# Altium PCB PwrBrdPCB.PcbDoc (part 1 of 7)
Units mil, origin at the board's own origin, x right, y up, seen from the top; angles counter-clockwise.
Board outline 8000 x 5500 mil, 4 copper layers (Top Layer, Internal 1, Internal 2, Bottom Layer), stack 61.834 mil thick; 682 components, 380 nets, 1899 pads, 766 vias.
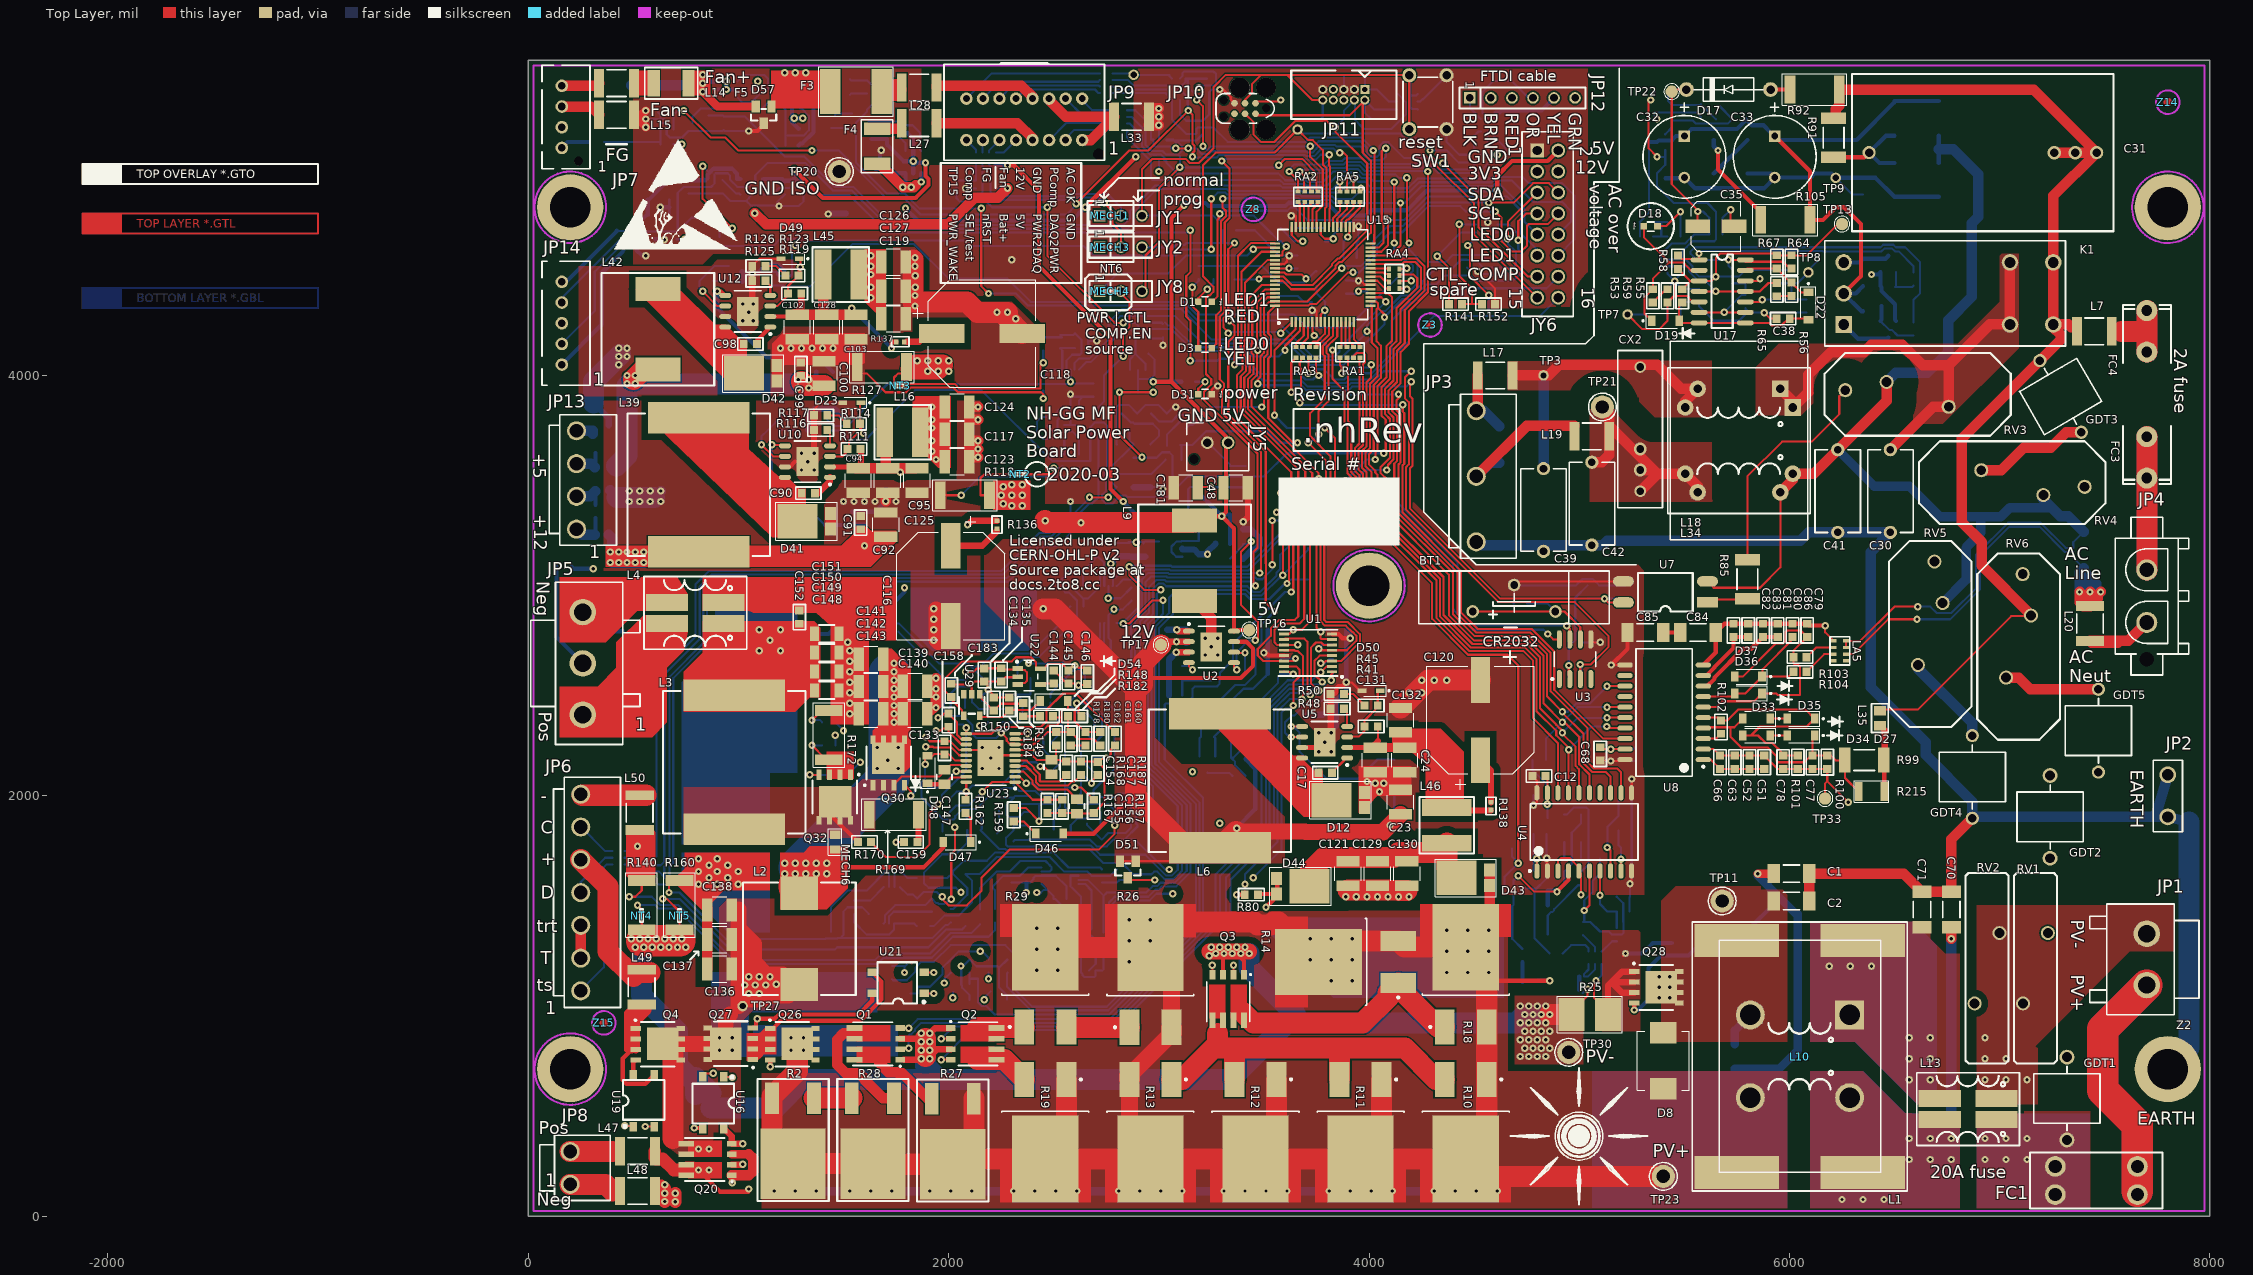
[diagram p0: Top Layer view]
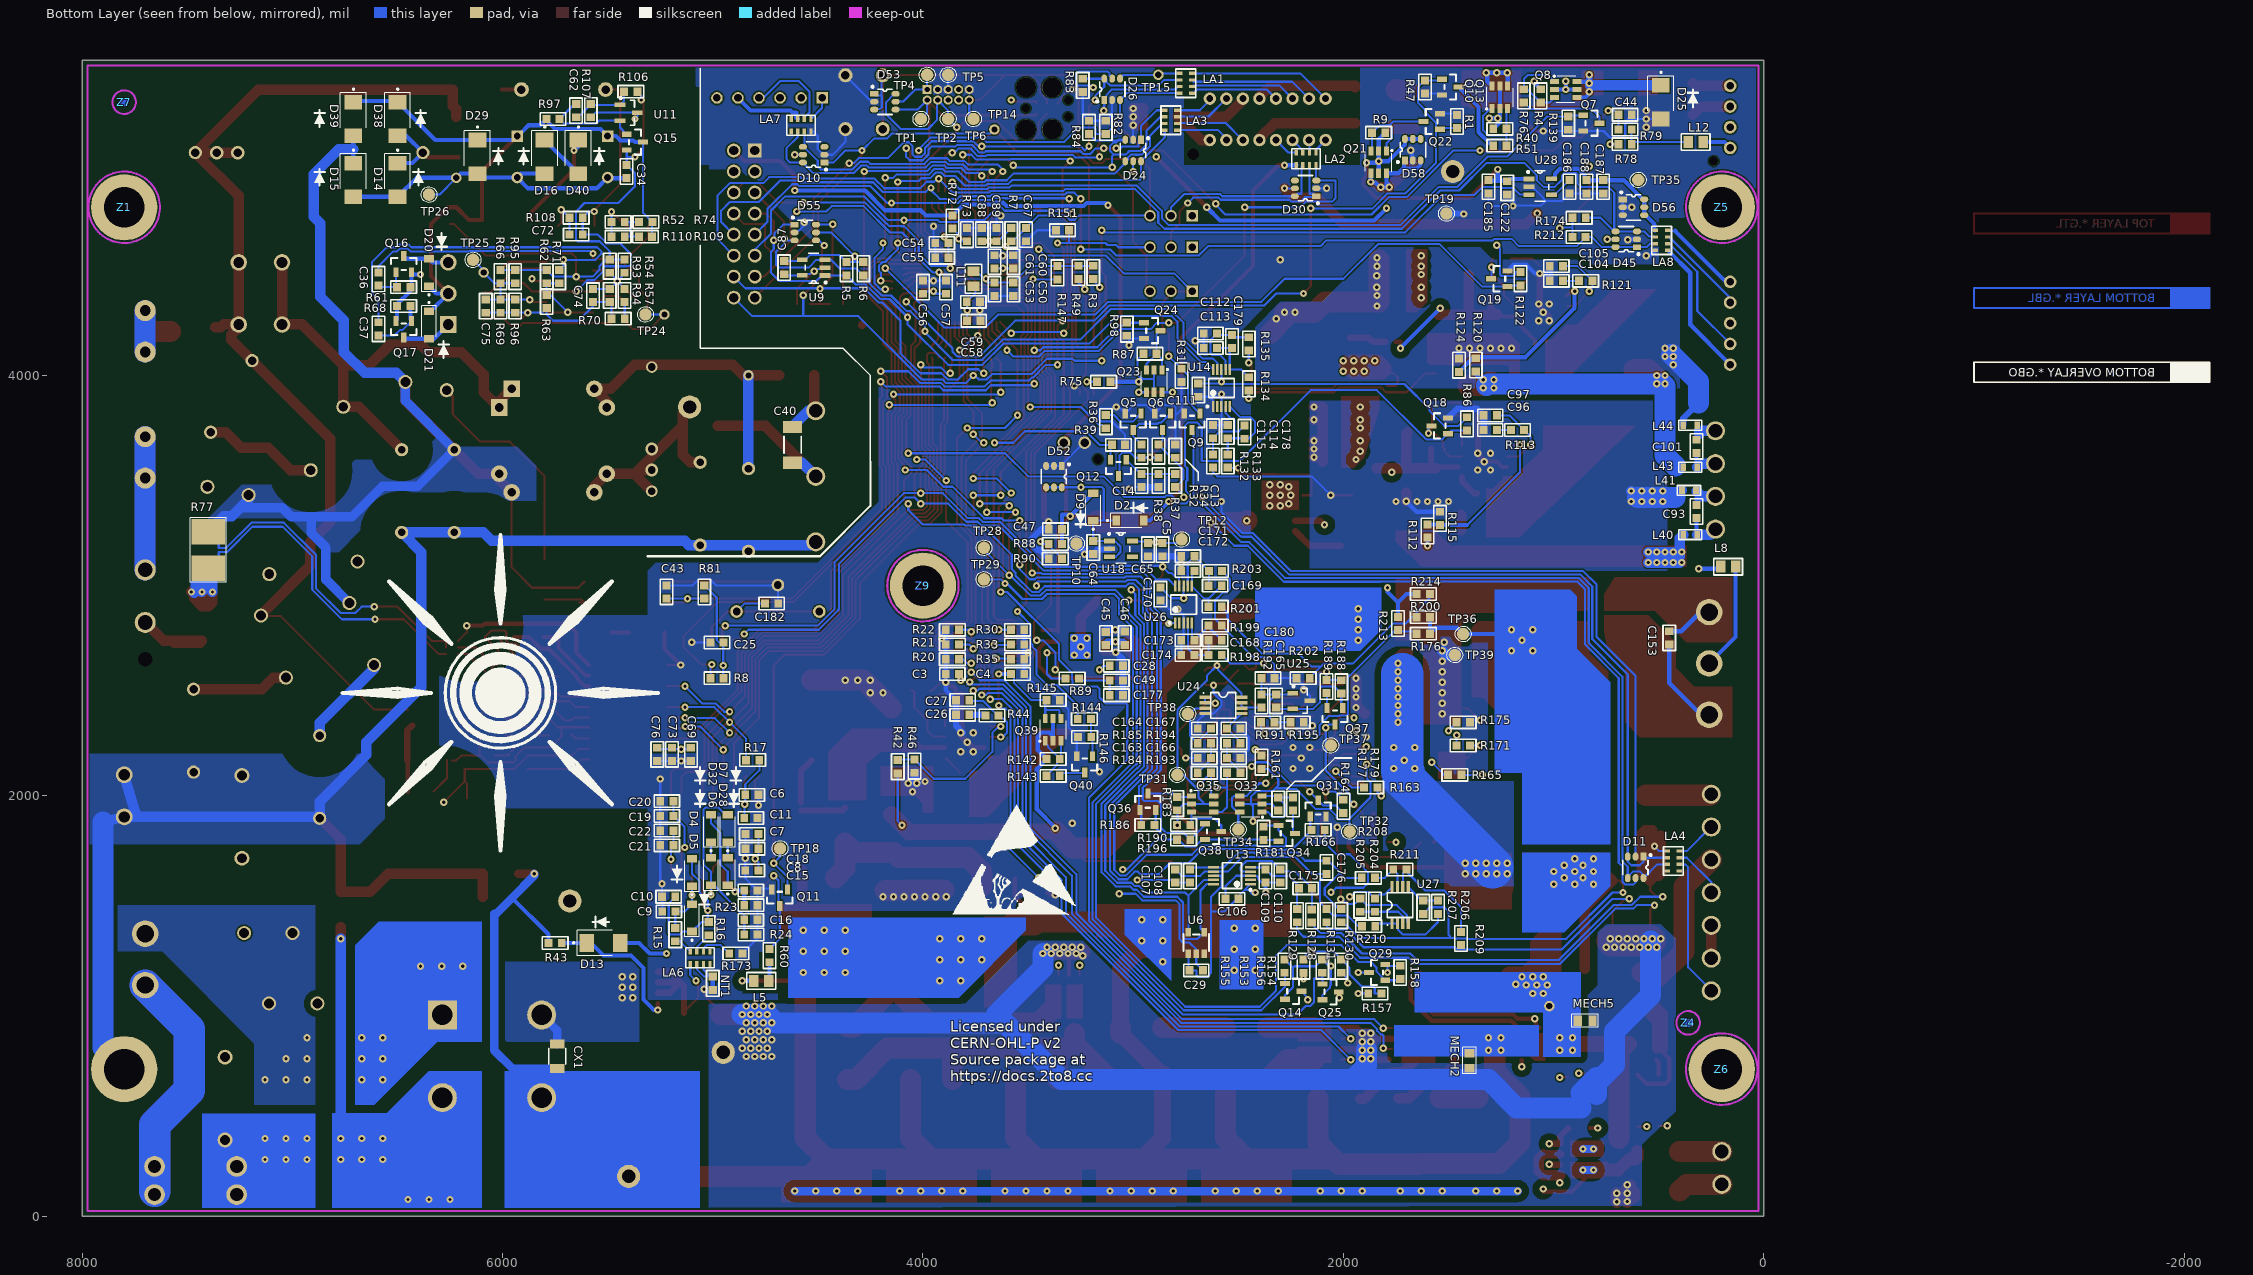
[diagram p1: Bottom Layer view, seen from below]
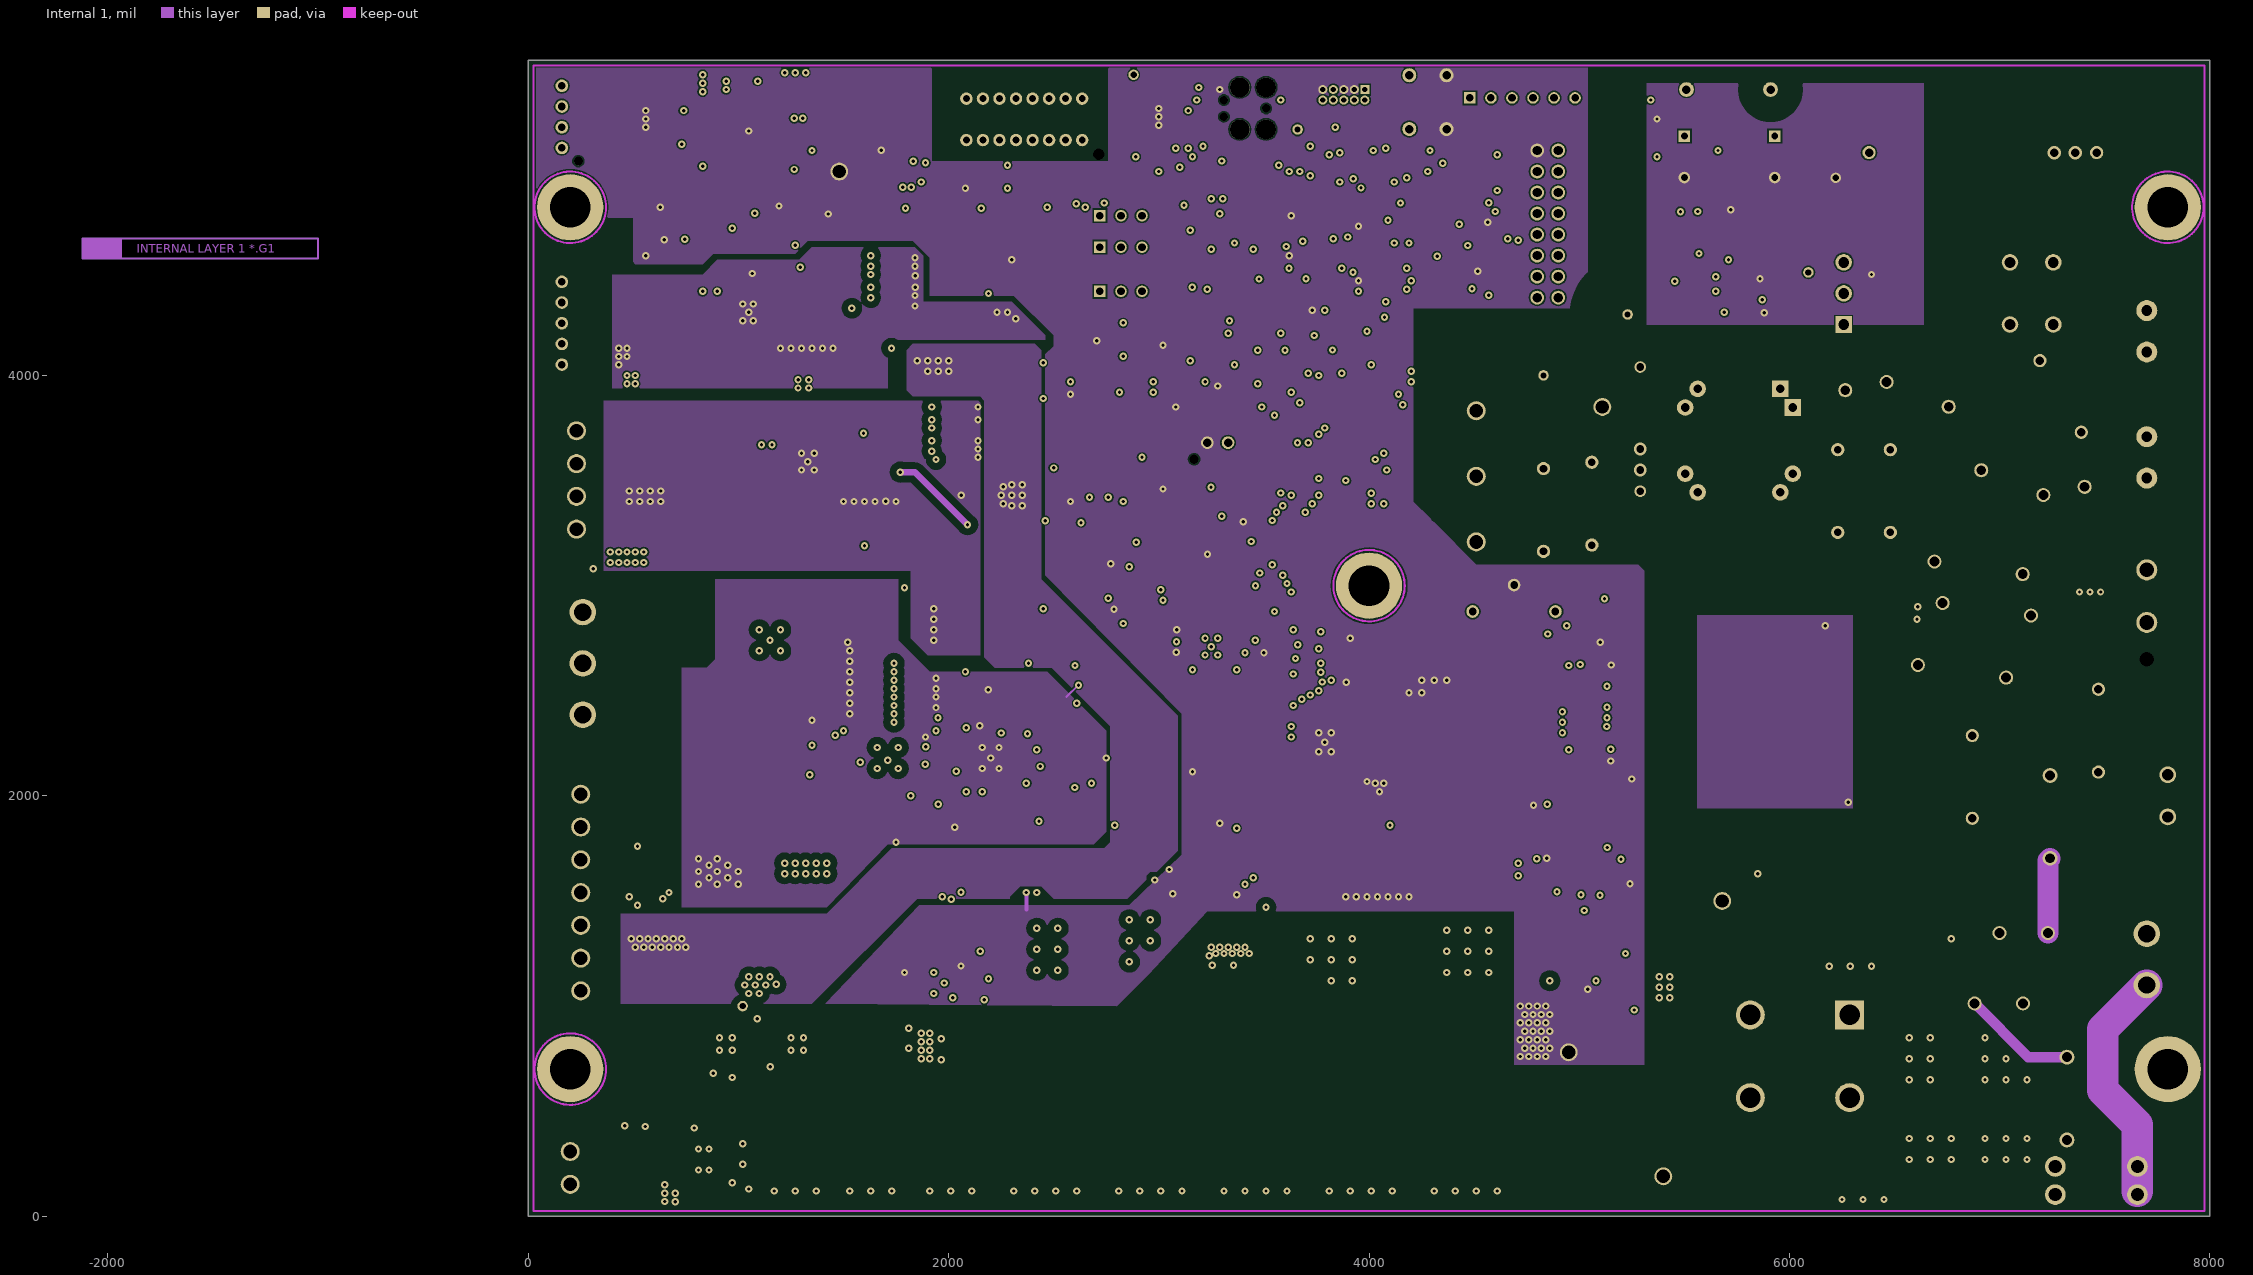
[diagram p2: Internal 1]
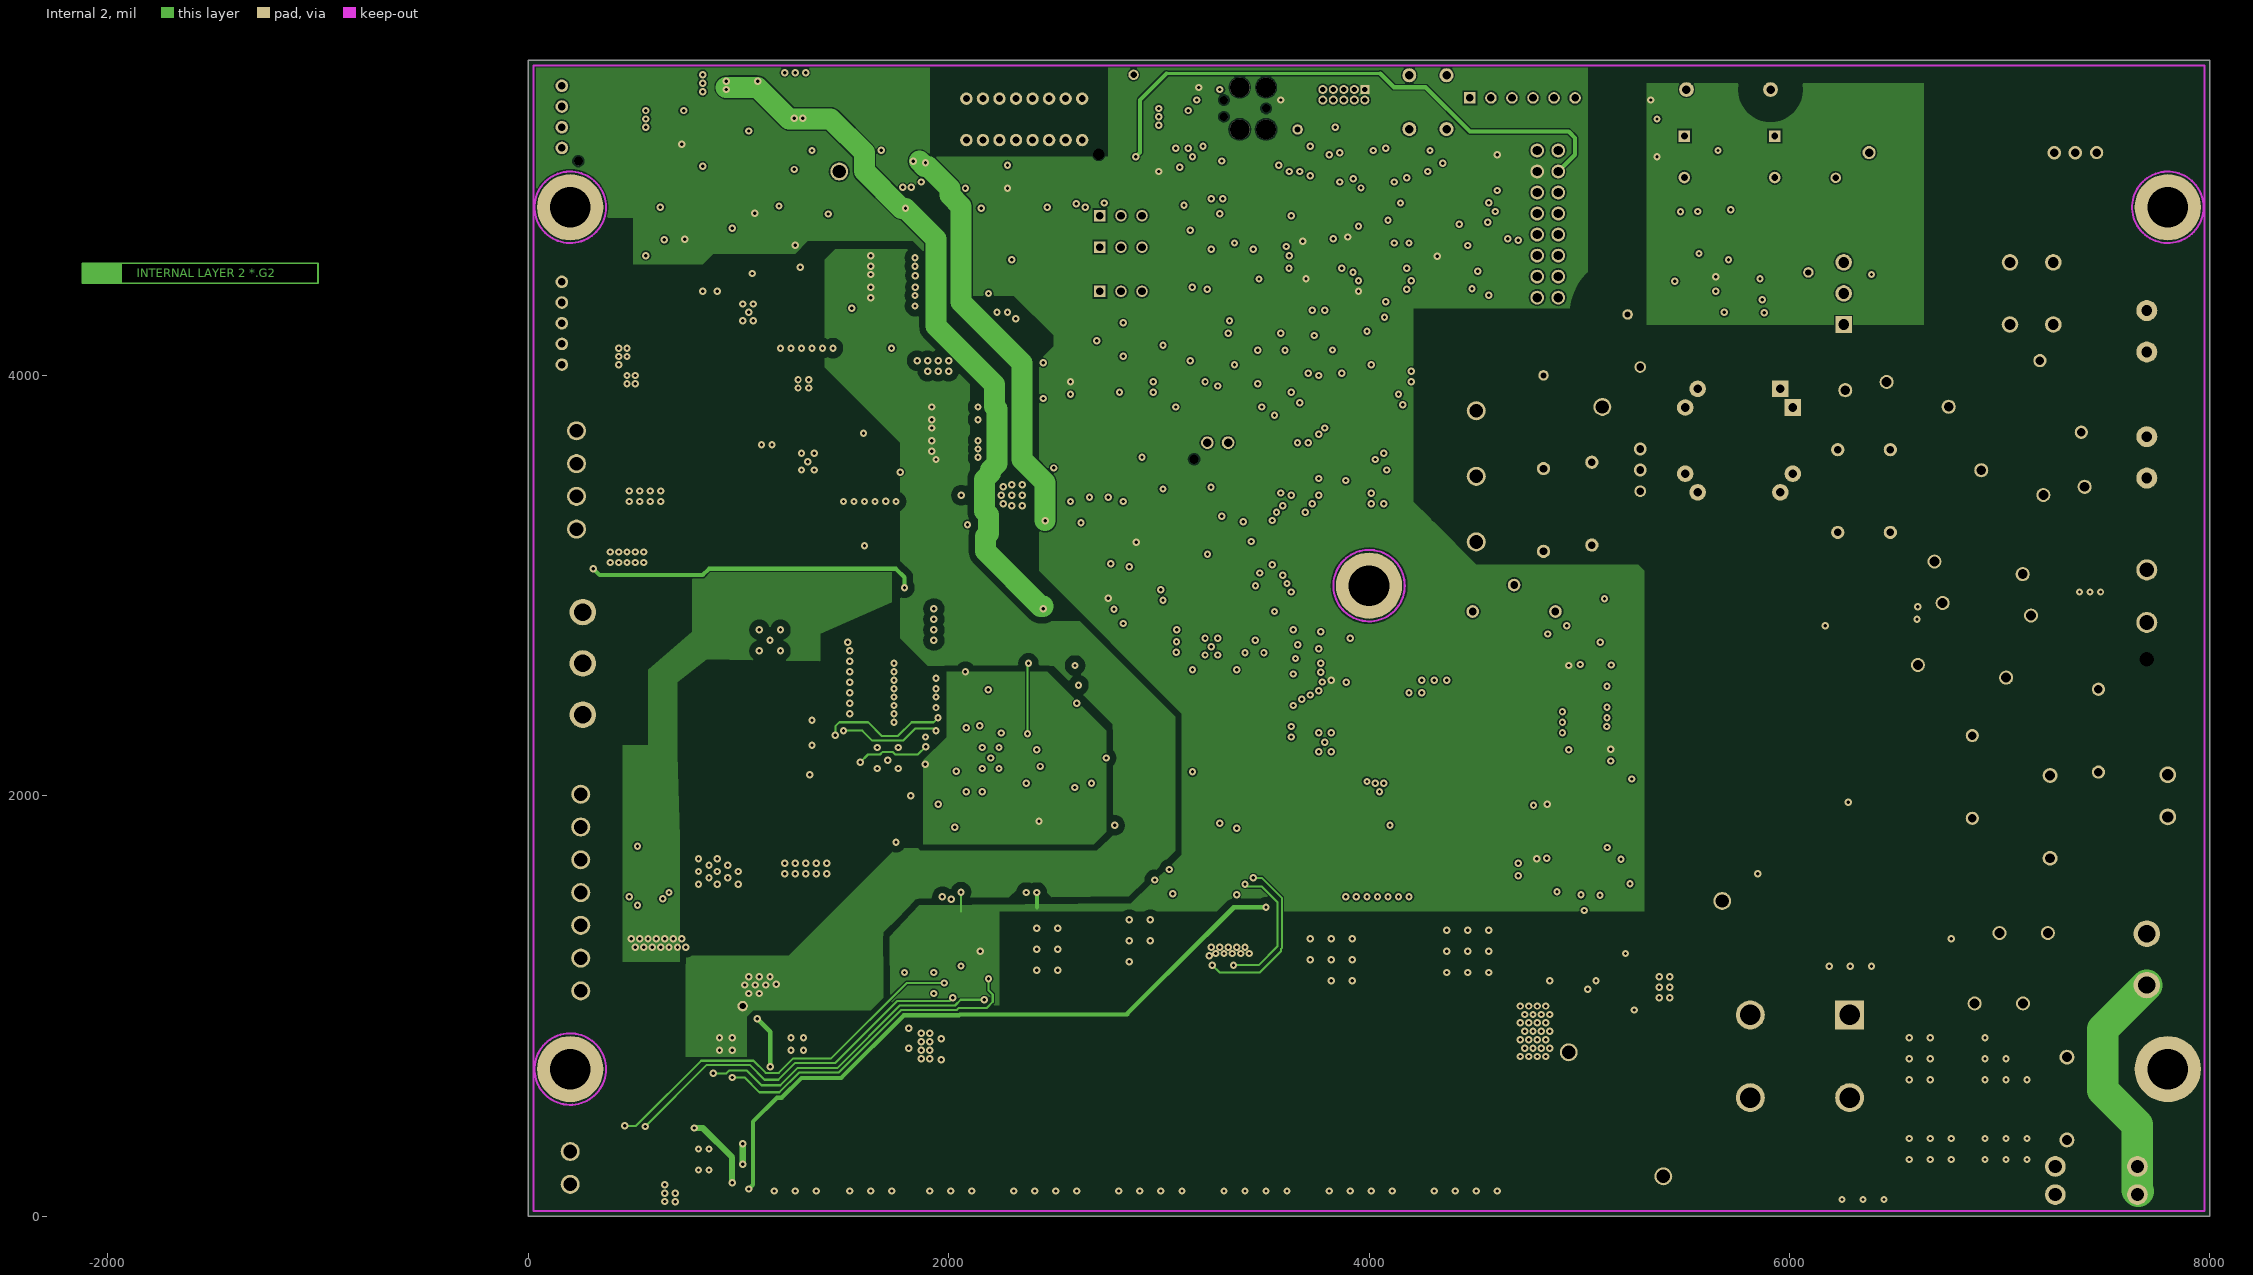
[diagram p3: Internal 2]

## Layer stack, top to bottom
Top Solder: solder mask 0.4, Solder Resist, Dk 3.5
Top Layer: signal copper 1.4
Dielectric 1: core 14.1, FR-4, Dk 4.2
Internal 1: signal copper 1.417
Dielectric 3: prepreg 28, FR-4, Dk 4.2
Internal 2: signal copper 1.417
Dielectric 2: core 14.1, FR-4, Dk 4.2
Bottom Layer: signal copper 1.4
Bottom Solder: solder mask 0.4, Solder Resist, Dk 3.5

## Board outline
0,0 0,5500 8000,5500 8000,0 3900,0 3500,0

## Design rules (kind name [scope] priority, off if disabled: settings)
AssemblyTestPointUsage [All] p1 off:
AssemblyTestpoint [All] p1 off: testpointundercomponent=TRUE minsize=40 maxsize=100 preferedsize=60 minholesize=0 maxholesize=40 preferedholesize=32 testpointgrid=1 usegrid=TRUE gridtolerance=0.01 allowsidetop=TRUE allowsidebottom=TRUE
Clearance Clearance_PVSELV [InNetClass('PVPOS') vs InNetClass('SELV')] p1: gap=32 ignorepadtopadclearanceinfootprint=TRUE // Super reinforced for separated extremely low voltage
Clearance Clearance_ProtCtl [InNetClass('LineUnprot') OR InNetClass('Neut') vs InNetClass('ProtCtrl')] p2: gap=120 ignorepadtopadclearanceinfootprint=TRUE // "functional" insulation for protection control traces
Clearance Clearance_LineSELV [InNetClass('LineProt') OR InNetClass('Neut') OR InNetClass('LineUnprot') OR InNetClass('ProtCtrl') vs InNetClass('SELV')] p3: gap=252 ignorepadtopadclearanceinfootprint=FALSE // Super reinforced for separated extremely low voltage
Clearance Clearance_PVtoEarth [InNetClass('PVPOS') vs InNetClass('Earth')] p4: gap=52 ignorepadtopadclearanceinfootprint=FALSE except(0: Arc-Hole Track-Hole SMDPad-Hole THPad-Hole Via-Hole Fill-Hole Poly-Hole Region-Hole Text-Hole) // "basic" insulation for PV to earth
Clearance Clearance_LProtToEarth [InNetClass('LineProt') vs InNetClass('Earth')] p5: gap=126 ignorepadtopadclearanceinfootprint=TRUE // "basic" insulation for protected side to earth
Clearance Clearance_LNUnprotEarth [InNetClass('LineUnprot') OR InNetClass('Neut') vs InNetClass('Earth')] p6: gap=166 ignorepadtopadclearanceinfootprint=TRUE // "basic" insulation for unprotected parts to Earth
Clearance Clearance_LNProt [InNetClass('LineProt') vs InNetClass('Neut')] p7: gap=118 ignorepadtopadclearanceinfootprint=TRUE // "functional" insulation for partsProtected by relay
Clearance Clearance_LUnProtN [InNetClass('LineUnprot') vs InNetClass('Neut')] p8: gap=166 ignorepadtopadclearanceinfootprint=TRUE // "basic" insulation for LN before relay
Clearance Clearance_innerPlanes [(OnLayer('Grounds') OR OnLayer('Powers'))] p9: gap=11 ignorepadtopadclearanceinfootprint=FALSE
Clearance [All] p10: gap=7 ignorepadtopadclearanceinfootprint=FALSE except(0: Arc-Hole Track-Hole SMDPad-Hole THPad-Hole Via-Hole Fill-Hole Poly-Hole Region-Hole Text-Hole)
FabricationTestPointUsage [All] p1 off: valid=0 allowmultiple=FALSE
FabricationTestpoint [All] p1 off: side=3 testpointundercomponent=TRUE minsize=40 maxsize=100 preferedsize=60 minholesize=0 maxholesize=40 preferedholesize=32 testpointgrid=1 allowsidetop=TRUE allowsidebottom=TRUE usegrid=TRUE gridtolerance=0.01
Height [All] p1 off: minheight=0 maxheight=1000 prefheight=500
HoleSize [All] p1: absolutevalues=TRUE maxlimit=200 minlimit=1 maxpercent=80.000 minpercent=20.000
PolygonConnect [All] p1: connectstyle=Direct reliefconductorwidth=10 reliefentries=4 polygonreliefangle="90 Angle" airgapwidth=10
RoomDefinition 12Vmain [InComponentClass('12Vmain')] p1: confinementstyle=ConfineIn formatcopy=TRUE lockcomponents=FALSE outline 2936.97,1664.23 2936.97,2479.63 3737.52,2479.63 3737.52,2498.94 3773.82,2498.94 3773.82,2528.46 4243.43,2528.46 4243.43,2690.28 4816.57,2690.28 4816.57,2017.5 4618.56,2017.5 4618.56,1507.58 3835.12,1507.58 3835.12,1468.22 3518.13,1468.22 3518.13,1486.53 3375.04,1486.53 3375.04,1664.23
RoomDefinition 5Vmain [InComponentClass('5Vmain')] p2: confinementstyle=ConfineIn formatcopy=TRUE lockcomponents=FALSE outline 2886.61,2835.47 2886.61,3401.54 3453.63,3401.54 3453.63,2838.86 3480.36,2838.86 3480.36,2738.15 3406.66,2738.15 3406.66,2589.25 3364.96,2589.25 3364.96,2515.04 3153.98,2515.04 3153.98,2505.04 3153.98,2435.04 3006.02,2435.04 3006.02,2668.15 2959.65,2668.15 2959.65,2835.47
RoomDefinition 3V3sup [InComponentClass('3V3sup')] p3: confinementstyle=ConfineIn formatcopy=TRUE lockcomponents=FALSE outline 2939.64,3361.85 3040.35,3361.85 3040.35,3266.16 3419.22,3266.16 3419.22,3043.23 3231.66,3043.23 3231.66,3094.08 2960.05,3094.08 2960.05,3097.52 2816.53,3097.52 2816.53,3245.47 2939.64,3245.47
RoomDefinition DCInput [InComponentClass('DCInput')] p4: confinementstyle=ConfineIn formatcopy=TRUE lockcomponents=FALSE outline 5261.21,537.94 5261.21,942.4 5415.04,942.4 5415.04,1513.47 5597.17,1513.47 5597.17,1582.83 5875,1582.83 5875,1696.1 7068.58,1696.1 7068.58,2149.17 7715.2,2149.17 7715.2,2183.94 7884.8,2183.94 7884.8,1499.76 7961.97,1499.76 7961.97,944.33 7789.96,944.33 7789.96,21.14 7130.04,21.14 7130.04,105.24 5522.4,105.24 5522.4,107.17 5317.17,107.17 5317.17,537.94
RoomDefinition PVMon [InComponentClass('PVMon')] p5: confinementstyle=ConfineIn formatcopy=TRUE lockcomponents=FALSE outline 4622.93,1371.01 4622.93,1528.6 4734.53,1528.6 4734.53,2138.11 4882.48,2138.11 4882.48,2070.91 5302.2,2070.91 5302.2,1445 5308.86,1445 5308.86,1344.29 5221.97,1344.29 5221.97,1265.04 5141.42,1265.04 5141.42,1152.99 4981.97,1152.99 4981.97,1066.53 4841.34,1066.53 4841.34,1046.69 4675.67,1046.69 4675.67,1371.01
RoomDefinition ACMon [InComponentClass('ACMon')] p6: confinementstyle=ConfineIn formatcopy=TRUE lockcomponents=FALSE outline 5060.63,2123.27 5060.63,2271.22 5161.81,2271.22 5161.81,2721.22 5179.09,2721.22 5179.09,2843.35 5690.63,2843.35 5690.63,2861.22 6127.56,2861.22 6127.56,2738.9 6160.71,2738.9 6160.71,2416.47 6178.76,2416.47 6178.76,2400.55 6466.93,2400.55 6466.93,2293.94 6461.26,2293.94 6461.26,2100.16 6219.88,2100.16 6219.88,1936.89 6117.56,1936.89 6117.56,1932.28 5890.63,1932.28 5890.63,1933.27 5820.63,1933.27 5610.63,1933.27 5610.63,1934.76 5540.63,1934.76 5540.63,2073.27 5161.81,2073.27 5161.81,2123.27
RoomDefinition ACInput [InComponentClass('ACInput')] p7: confinementstyle=ConfineIn formatcopy=TRUE lockcomponents=FALSE outline 4354.32,3116.06 4354.32,3923.94 4472.87,3923.94 4472.87,4089.72 5169.76,4089.72 5169.76,4132.68 5418.23,4132.68 5418.23,4177.44 6153.22,4177.44 6153.22,4653.94 7326.77,4653.94 7326.77,4373.94 7829.17,4373.94 7829.17,4028.27 7838.94,4028.27 7838.94,3338.94 7913.94,3338.94 7913.94,2561.06 7641.42,2561.06 7641.42,2064.76 7041.42,2064.76 7041.42,1844.76 6698.58,1844.76 6698.58,2301.34 6458.15,2301.34 6458.15,3109.84 4705.83,3109.84 4705.83,3116.06
RoomDefinition Aux12V [InComponentClass('Aux12V')] p8: confinementstyle=ConfineIn formatcopy=TRUE lockcomponents=FALSE outline 457.91,3072.3 457.91,3887.7 1940.02,3887.7 1940.02,3924.96 2139.7,3924.96 2139.7,3517.76 2243.62,3517.76 2243.62,3345.28 2267.56,3345.28 2267.56,3341.56 2296.57,3341.56 2296.57,2668.78 1723.43,2668.78 1723.43,3072.3
RoomDefinition U_HVAUX [InComponentClass('U_HVAUX')] p9: confinementstyle=ConfineIn formatcopy=TRUE lockcomponents=FALSE outline -1.97,2230.24 -1.97,3029.76 87.17,3029.76 87.17,3143.31 252.83,3143.31 252.83,3058.23 1054.06,3058.23 1054.06,2923.98 1333.46,2923.98 1333.46,2894.96 1783.47,2894.96 1783.47,2658.12 2480.6,2658.12 2480.6,2641.39 2713.46,2641.39 2713.46,2440.35 2790.35,2440.35 2790.35,2345.48 2834.96,2345.48 2834.96,2150.35 2840.35,2150.35 2840.35,2050.1 3006.44,2050.1 3006.44,1892.51 3004.96,1892.51 3004.96,1818.03 2834.96,1818.03 2834.96,1748.03 2423.46,1748.03 2423.46,1746.54 2348.99,1746.54 2348.99,1745.92 2164.67,1745.92 2164.67,1731.66 1573.63,1731.66 1573.63,1003.9 1006.61,1003.9 1006.61,1101.57 810.3,1101.57 810.3,1313.5 632.24,1313.5 632.24,1752.3 626.42,1752.3 626.42,2230.24
RoomDefinition Aux5V [InComponentClass('Aux5V')] p10: confinementstyle=ConfineIn formatcopy=TRUE lockcomponents=FALSE outline 333.49,3936.97 333.49,4503.03 913.15,4503.03 913.15,4563.47 1022.16,4563.47 1338.27,4563.47 1338.27,4624.92 1635.98,4624.92 1635.98,4614.96 1836.82,4614.96 1836.82,4486.57 2489.33,4486.57 2489.33,2421.97 2540.76,2421.97 2540.76,2335.04 2390.84,2335.04 2390.84,3910.02 1332.17,3910.02 1332.17,3936.97
RoomDefinition U_ACProtection [InComponentClass('U_ACProtection')] p11: confinementstyle=ConfineIn formatcopy=TRUE lockcomponents=FALSE outline 5195,4255 5195,4325 5243.54,4325 5243.54,4773.47 5282.31,4773.47 5282.31,5309.84 5312.24,5309.84 5312.24,5339.72 5315.04,5339.72 5315.04,5393.47 5389.65,5393.47 5389.65,5400.35 5459.84,5400.35 5459.84,5429.06 5953.5,5429.06 5953.5,5447.76 6282.95,5447.76 6282.95,5449.02 7557.05,5449.02 7557.05,4670.98 6633.47,4670.98 6633.47,4147.52 6545.58,4147.52 6545.58,4141.4 6393.56,4141.4 6393.56,4141.73 6301.66,4141.73 6301.66,4199.58 5508.69,4199.58 5508.69,4210.77 5285.33,4210.77 5285.33,4239.65 5269.65,4239.65 5269.65,4255
RoutingVias [All] p1: holewidth=16 width=35 viastyle="Through Hole" minholewidth=16 minwidth=35 maxholewidth=50 maxwidth=70
SMDNeckDown [All] p1: percent=90.000
SilkToSilkClearance [All] p1 off: silktosilkclearance=10
SilkToSolderMaskClearance [IsPad] p1: minsilkscreentomaskgap=5 clearancetoexposedcopper=TRUE
SolderMaskExpansion [All] p1: expansion=4 istentingtop=FALSE
Width WidthPVPos [InNetClass('PVPOS')] p1: maxlimit=200 minlimit=20 preferedwidth=20
Width [All] p2: maxlimit=300 minlimit=7 preferedwidth=10
22 further rules are at their usual default settings.

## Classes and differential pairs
component class U_HVAUX: C133 C134 C135 C136 C137 C138 C139 C140 C141 C142 C143 C144 C145 C146 C147 C148 C149 C150 C151 C152 C153 C154 C155 C156 C157 C158 C159 C160 C161 C162 C163 C164 C165 C166 C167 C180 C183 C184 D46 D47 D48 D54 JP5 L2 L3 L4 L8 MECH6 Q30 Q31 Q32 Q33 Q34 Q35 Q36 Q37 Q38 R148 R149 R150 R159 R160 R161 R162 R163 R164 R165 R166 R167 R168 R169 R170 R171 R172 R175 R176 R177 R178 R179 R180 R181 R182 R183 R184 R185 R186 R187 R188 R189 R190 R191 R192 R193 R194 R195 R196 R197 R213 TP31 TP32 TP34 TP36 TP37 TP38 TP39 U22 U23 U24 U25 U29
component class PVMon: C6 C7 C8 C9 C10 C11 C12 C15 C16 C18 C19 C20 C21 C22 D4 D5 D6 D7 D28 D32 L5 LA6 Q11 Q40 R15 R16 R23 R24 R60 TP10 U4
component class DCInput: C1 C2 C70 C71 CX1 F1 FC1 GDT1 GDT2 JP1 JP2 L1 L10 L13 R43 RV1 RV2 TP11 TP23
component class ACMon: C51 C52 C63 C66 C68 C69 C73 C76 C77 C78 C79 C80 C81 C82 C83 C84 C85 C86 D27 D33 D34 D35 D36 D37 L35 LA5 R99 R100 R101 R102 R103 R104 R215 TP33 U8
component class ACInput: C30 C39 C40 C41 C42 CX2 F2 FC3 FC4 GDT3 GDT4 GDT5 JP3 JP4 K1 L7 L17 L18 L19 L20 L34 R77 RV3 RV4 RV5 RV6 TP3 TP21
component class Aux12V: C90 C91 C92 C94 C95 C96 C97 C116 C117 C123 C124 C125 L16 L39 Q18 R86 R111 R113 R114 R115 R116 R117 R118 R136
component class Aux5V: C98 C99 C100 C102 C103 C104 C105 C118 C119 C126 C127 C128 L42 L45 Q19 R119 R120 R121 R122 R123 R124 R125 R126 R127 R137 R148
component class U_HVAUXMORE: C106 C107 C108 C109 C110 C122 C168 C169 C170 C171 C172 C173 C174 C175 C176 C185 C186 C187 C188 D45 D56 JP14 LA8 NT4 NT5 R128 R129 R130 R131 R174 R198 R199 R200 R201 R202 R203 R204 R205 R206 R207 R208 R209 R210 R211 R212 R214 TP35 U13 U26 U27 U28
component class U_Peripherals: BT1 C25 C50 C53 C54 C55 C56 C57 C58 C59 C60 C61 C87 C88 C89 C182 L11 R5 R6 R8 U3 U9
component class U_DCPower: C1 C2 C13 C14 C70 C71 CX1 D8 D11 D13 FC1 GDT1 GDT2 JP1 JP2 JP6 JP8 L1 L10 L13 L47 L48 L49 L50 LA4 MECH2 MECH5 NT1 Q4 Q5 Q6 Q9 Q12 Q14 Q20 Q23 Q24 Q25 Q26 Q27 Q28 Q29 R25 R31 R32 R34 R36 R37 R38 R39 R43 R87 R98 R140 R153 R154 R155 R156 R157 R158 RV1 RV2 TP11 TP23 TP27 TP30 U16 U19 U21
component class U_DCMonitoring: C3 C4 C6 C7 C8 C9 C10 C11 C12 C15 C16 C18 C19 C20 C21 C22 C29 D4 D5 D6 D7 D28 D32 L5 LA6 Q1 Q2 Q3 Q11 Q39 Q40 R2 R10 R11 R12 R13 R14 R15 R16 R18 R19 R20 R21 R22 R23 R24 R26 R27 R28 R29 R30 R33 R35 R60 R142 R143 R144 R145 R146 R173 TP10 TP18 U1 U4 U6
component class U_LVPower: C5 C17 C23 C24 C26 C27 C28 C44 C45 C46 C47 C48 C49 C64 C65 C120 C121 C129 C130 C131 C132 C177 C181 D2 D9 D12 D25 D31 D43 D44 D50 D51 D52 D57 D58 F3 F4 F5 JP7 JY5 L6 L9 L12 L14 L15 L46 Q7 Q8 Q10 Q13 Q21 Q22 R1 R4 R9 R40 R41 R42 R44 R45 R46 R47 R48 R50 R51 R75 R76 R78 R79 R80 R88 R89 R90 R138 R139 TP12 TP16 TP17 TP19 TP20 U2 U5 U18
net class Earth: GND
net class PVPOS: 24V DCBUS DR0 DR1 DR2 DR3 DR4 DR5 HVX_DCBUS HVX_HB HVX_SW HVX_VOUT NetC17_1 NetC17_2 NetC24_1 NetC90_1 NetC90_2 NetC94_1 NetC98_1 NetC98_2 NetC102_1 NetC116_+ NetC118_+ NetC120_+ NetC121_1 NetC153_1 NetFC1_2 NetGDT1_2 NetL5_2 NetL49_1 NetQ4_G NetQ20_1 NetQ20_2 NetR2_1 NetR26_1 POS1 PV_SEL+ PV_SEL- PVPOS PVPROT
net class SELV: 3V3_ANA 3V3_AUX3 3V3_ISO 3V3_LOAD 5V_AUX2 5V_COMP 5V_ISO 5V_MAIN 12V_AUX1 12V_AVAIL 12V_ISO 12V_MAIN COMP.EN COMP.RX COMP.TX COMP_D COMP_ENABLE COMP_T CTL_COMP CTL_PCOMP DC_OK DCMON.N3 FAN_CTL FAN_DRAIN FAN_GATE FAN_LOCKED FAN_ON FG1 GND_AUX1 GND_AUX2 GND_AUX3 GND_COMP GND_ISO GT0 GT1 GT2 GT3 GT4 GT5 HVAUX.DEMB HVAUX.E\N\ HVAUX.FC0 HVAUX.FC1 HVAUX.ISET HVAUX.UART_A2P HVAUX.UART_P2A HVAUX.VSET HVX_1V65 HVX_CM HVX_COMP HVX_DEMB HVX_FB HVX_RAMP HVX_RES HVX_RT HVX_SS HVX_UVLO HVX_VIN HVX_VOUT I2C.SCL I2C.SDA LED0 LED1 MON.ADC_CLK MON.C\S\_MAINS MON.C\S\_PV MON.CAL MON.D\R\_PV MON.MISO MON.MOSI MON.MOV_BAD MON.SCLK NEG1 NEG2 NetBT1_+ NetC14_1 NetC26_1 NetC27_1 NetC28_1 NetC49_1 NetC64_1 NetC93_1 NetC93_2 NetC96_1 NetC97_1 NetC101_1 NetC101_2 NetC104_1 NetC105_1 NetC107_1 NetC108_1 NetC109_1 NetC110_1 NetC112_1 NetC113_1 NetC114_1 NetC115_1 NetC144_1 NetC162_1 NetC163_1 NetC164_1 NetC165_1 NetC165_2 NetC166_1 NetC167_1 NetC168_1 NetC168_2 NetC169_1 NetC169_2 NetC184_1 NetC186_1 NetD1_A NetD3_A NetD6_A NetD7_K NetD13_K NetD23_K NetD31_A NetD49_K NetD50_K NetD57_1 NetD58_1 NetF5_2 NetGDT2_1 NetJP7_1 NetJP7_3 NetJP7_4 NetJP9_1 NetJP9_2 NetJP9_3 NetJP9_4 NetJP9_5 NetJP9_7 NetJP9_8 NetJP9_9 NetJP9_10 NetJP9_11 NetJP9_12 NetJP9_13 NetJP9_14 NetJP9_15 NetJP9_16 NetJP12_1 NetJP12_4 NetJP12_5 NetJP14_1 NetJP14_2 NetJP14_4 NetJP14_5 NetL8_1 NetL9_1 NetLA6_6 NetLA6_7 NetLA6_8 NetNT2_2 NetNT3_2 NetNT4_2 NetNT5_2 NetQ5_1 NetQ5_3 NetQ7_3 NetQ10_3 NetQ13_1 NetQ21_1 NetQ23_1 NetQ29_3 NetQ33_1 NetQ34_3 NetQ35_1 NetQ35_3 NetQ35_4 NetQ35_6 NetQ37_2 NetQ39_1 NetQ40_1 NetQ40_3 NetR42_2 NetR45_1 NetR48_1 NetR88_1 NetR89_2 NetR112_2 NetR114_1 NetR116_1 NetR120_2 NetR123_1 NetR125_1 NetR148_2 NetR149_2 NetR157_1 NetR161_1 NetR182_2 NetR192_1 NetR200_2 NetR204_2 NetR206_1 NetR208_1 NetR209_2 NetRA1_1 NetRA1_2 NetRA1_3 NetRA1_4 NetRA2_5 NetRA2_6 NetRA2_7 NetRA2_8 NetRA3_1 NetRA3_2 NetRA3_3 NetRA3_4 NetRA4_1 NetRA4_2 NetRA4_3 NetRA4_4 NetRA5_5 NetRA5_6 NetRA5_7 NetRA5_8 NRESET PVMON_IA+ PVMON_IA- PVMON_LDO PVMON_REF PVMON_V+ PVMON_V- PVNEG PWR_AVAIL.BIT0 PWR_AVAIL.BIT1 PWR_AVAIL.BIT2 PWR_AVAIL.BIT3 PWR_AVAIL.BIT4 PWR_AVAIL.BIT5 PWR_NRST PWR_SEL.5VAUX_E\N\ PWR_SEL.12VAUX_E\N\ PWR_SEL.COMP_PWRD PWR_SEL.MAINBRD_EN PWR_SEL.SEL_AC PWR_SEL.SEL_PV PWR_SELECT PWR_WAKE RTC_INT SWCLK SWDIO TEST_MODE TP15 UART2_RXD UART2_TXD UART_DAQ2PWR UART_PWR2DAQ VBAT_UNREG VCC_AUX3 VCORE WAKE_INT
component class U_Microcontroller: C67 D1 D3 D10 D24 D26 D30 D53 D55 JP9 JP10 JP11 JP12 JY1 JY2 JY6 JY8 L27 L28 L33 LA1 LA2 LA3 LA7 NT6 R3 R7 R17 R49 R72 R73 R82 R83 R84 R147 R151 RA1 RA2 RA3 RA4 RA5 SW1 TP1 TP2 TP4 TP5 TP6 TP14 TP15 TP28 TP29 U15
component class Cover: MECH1 MECH3 MECH4 R141 R152 Z1 Z2 Z3 Z4 Z5 Z6 Z7 Z8 Z9 Z14 Z15 Z16 Z17 Z18 Z19 Z20 Z21 Z22 Z23 Z24 Z25 Z26 Z27 Z28 Z29 Z30 Z31
component class U_ACProtection: C31 C32 C33 C34 C35 C36 C37 C38 C62 C72 C74 C75 D14 D15 D16 D17 D18 D19 D20 D21 D22 D29 D38 D39 D40 Q15 Q16 Q17 R52 R53 R54 R55 R56 R57 R58 R59 R61 R62 R63 R64 R65 R66 R67 R68 R69 R70 R71 R74 R91 R92 R93 R94 R95 R96 R97 R105 R106 R107 R108 R109 R110 TP7 TP8 TP9 TP13 TP22 TP24 TP25 TP26 U11 U17
net class LineUnprot: L1 MOV3 NetD17_A NetFC4_1 NetGDT3_2 NetGDT4_1 NetGDT5_1 NetL35_2 PROT.LFUSED
net class ProtCtrl: GND_PROT input_ok NetC31_2 NetC36_1 NetC37_1 NetC62_1 NetC62_2 NetD16_K NetD18_A NetD40_K NetR52_2 NetR53_2 NetR56_2 NetR57_1 NetR62_1 NetU17_3 NetU17_12 overvoltage# PROT.RESET PROT.SET ref_high ref_low reset sense_prot set undervoltage# Vcc_prot Vcoil
component class U_ACPower: C30 C39 C40 C41 C42 C43 C51 C52 C63 C66 C68 C69 C73 C76 C77 C78 C79 C80 C81 C82 C83 C84 C85 C86 CX2 D27 D33 D34 D35 D36 D37 FC3 FC4 GDT3 GDT4 GDT5 JP3 JP4 K1 L7 L17 L18 L19 L20 L34 L35 LA5 R77 R81 R85 R99 R100 R101 R102 R103 R104 R215 RV3 RV4 RV5 RV6 TP3 TP21 TP33 U7 U8
net class LineProt: L2 Lfiltered LPROT
net class Neut: GND_MON MON_IA+ MON_IA- MON_LDO MON_REF MON_V+ MON_V- MOV1 MOV2 MOV4 N1 N2 NetD27_A NetD33_K NetLA5_6 NetLA5_7 NetR85_1 NetR102_1 Nfiltered Nin PROT.NPROT VDDMON
component class U_AuxOutput: C90 C91 C92 C93 C94 C95 C96 C97 C98 C99 C100 C101 C102 C103 C104 C105 C111 C112 C113 C114 C115 C116 C117 C118 C119 C123 C124 C125 C126 C127 C128 C178 C179 D23 D41 D42 D49 JP13 L16 L39 L40 L41 L42 L43 L44 L45 NT2 NT3 Q18 Q19 R86 R111 R112 R113 R114 R115 R116 R117 R118 R119 R120 R121 R122 R123 R124 R125 R126 R127 R132 R133 R134 R135 R136 R137 U10 U12 U14
component class 3V3sup: C5 C64 C65 D2 D9 TP12
component class 5Vmain: C28 C45 C46 C49 C177 L9 R88 R89 R90 TP16 TP17 TP18 TP28 TP29 TP31 TP32 TP34 TP35 TP36 TP37 TP38 TP39 U2
component class 12Vmain: C17 C23 C24 C26 C27 C120 C121 C129 C130 C131 C132 L6 L46 R41 R42 R44 R45 R46 R48 R50 R80 R138

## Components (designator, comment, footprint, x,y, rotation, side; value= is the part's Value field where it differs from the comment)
BT1 "20mm cell" HARWIN_S8401-46 4690,2940 r90 top
C1 "250VAC X1/Y2" CAPC4720X22N 6010,1630 r0 top value=1E-9
C2 "250VAC X1/Y2" CAPC4720X22N 6010,1500 r180 top value=1E-9
C3 "50V X7R 0603" CAPC1608X09N[0603] 3860,2580 r0 bottom value=1E-7
C4 "50V X7R 0603" CAPC1608X09N[0603] 3550,2580 r180 bottom value=1E-7
C5 "50V X7R 0603" CAPC1608X09N[0603] 2860,3171.5 r270 bottom value=1E-7
C6 "25V X6S 0603" CAPC1608X09N[0603] 4814.02,2004.65 r0 bottom value=4.7E-6
C7 "25V X6S 0603" CAPC1608X09N[0603] 4813.07,1818.5 r0 bottom value=4.7E-6
C8 "50V X7R 0603" CAPC1608X09N[0603] 4814.02,1644.65 r0 bottom value=1E-7
C9 "50V X7R 0603" CAPC1608X09N[0603] 5208.5,1450 r0 bottom value=3.3E-8
C10 "50V X7R 0603" CAPC1608X09N[0603] 5210,1520 r180 bottom value=3.3E-8
C11 "25V X6S 0603" CAPC1608X09N[0603] 4818.5,1894.65 r0 bottom value=4.7E-6
C12 "50V X7R 0603" CAPC1608X09N[0603] 4808.5,2094.65 r0 top value=1E-7
C13 "50V C0G 0603" CAPC1608X09N[0603] 2800,3640 r90 bottom value=1E-8
C14 "50V C0G 0603" CAPC1608X09N[0603] 2960,3500 r270 bottom value=3.3E-11
C15 "50V X7R 0603" CAPC1608X09N[0603] 4818.5,1550 r180 bottom value=3.3E-8
C16 "50V X7R 0603" CAPC1608X09N[0603] 4818.5,1410 r180 bottom value=3.3E-8
C17 "50V X7R 0603" CAPC1608X09N[0603] 3791.5,2110 r180 top value=1E-7
C18 "25V X6S 0603" CAPC1608X09N[0603] 4813.07,1748.5 r0 bottom value=4.7E-6
C19 "50V X7R 0603" CAPC1608X09N[0603] 5218.5,1904.65 r0 bottom value=1E-7
C20 "25V X6S 0603" CAPC1608X09N[0603] 5218.5,1974.65 r0 bottom value=4.7E-6
C21 "50V X7R 0603" CAPC1608X09N[0603] 5218.5,1764.65 r0 bottom value=1E-7
C22 "25V X6S 0603" CAPC1608X09N[0603] 5218.5,1834.65 r0 bottom value=4.7E-6
C23 "16V  X5R 1210" CAPC3225X270 4150,1970 r90 top value=4.7E-5
C24 "100V X5R 1210" CAPC3225X270 4170,2170 r270 top value=4.7E-6
C25 "50V X7R 0603" CAPC1608X09N[0603] 4980,2730 r0 bottom value=1E-7
C26 "50V X7R 0603" CAPC1608X09N[0603] 3811.5,2385.47 r0 bottom value=2.2E-8
C27 "50V C0G 0603" CAPC1608X09N[0603] 3811.5,2455.47 r0 bottom value=1.6E-11
C28 "50V X7R 0603" CAPC1608X09N[0603] 3080,2618.5 r180 bottom value=1E-7
C29 "50V X7R 0603" CAPC1608X09N[0603] 2700,1170 r180 bottom value=1E-7
C30 "400VAC X1 Y1" CAP_RAD10P_DISC_10x5.5 6480,3450 r270 top value=2.2E-9
C31 "760VAC X1" KEMET_PHE845VF6330MR06L2 6920,5060 r180 top value=3.3E-7
C32 "35V 20% 105C" CAP_RB5/10MMX20MM 5500,5040 r90 top value=0.00047
C33 "35V 20% 105C" CAP_RB5/10MMX20MM 5930,5040 r90 top value=0.00047
C34 "25V X6S 0603" CAPC1608X09N[0603] 5410,4970 r270 bottom value=4.7E-6
C35 "35V 20% 1 ohm" CAP_ALUM_SIZE-SVPF-B6 5650,4710 r0 top value=2.2E-5
C36 "50V X7R 0603" CAPC1608X09N[0603] 6590,4458.5 r90 bottom value=3.3E-8
C37 "50V X7R 0603" CAPC1608X09N[0603] 6590,4221.5 r90 bottom value=3.3E-8
C38 "25V X6S 0603" CAPC1608X09N[0603] 5970,4270 r180 top value=4.7E-6
C39 "400VAC X1 Y1" CAP_RAD10P_DISC_10x5.5 4830,3360 r270 top value=2.2E-9
C40 "250VAC X1/Y2" CAPC4720X22N 4620,3670 r90 bottom value=2.2E-10
C41 "400VAC X1 Y1" CAP_RAD10P_DISC_10x5.5 6230,3450 r90 top value=2.2E-9
C42 "400VAC X1 Y1" CAP_RAD10P_DISC_10x5.5 5060,3390 r90 top value=2.2E-9
C43 "25V X6S 0603" CAPC1608X09N[0603] 5220,2970 r90 bottom value=4.7E-6
C44 "50V X7R 0603" CAPC1608X09N[0603] 660,5240 r180 bottom value=1E-7
C45 "25V X6S 0603" CAPC1608X09N[0603] 3130,2748.5 r90 bottom value=4.7E-6
C46 "25V X6S 0603" CAPC1608X09N[0603] 3040,2750 r90 bottom value=4.7E-6
C47 "50V X7R 0603" CAPC1608X09N[0603] 3370,3268.5 r0 bottom value=1E-7
C48 "16V  X5R 1210" CAPC3225X270 3365.8,3465.52 r0 top value=4.7E-5
C49 "50V C0G 0603" CAPC1608X09N[0603] 3080,2548.5 r180 bottom value=1E-9
C50 "50V X7R 0603" CAPC1608X09N[0603] 3570,4410 r270 bottom value=3.3E-8
C51 "25V X6S 0603" CAPC1608X09N[0603] 5880,2160 r90 top value=4.7E-6
C52 "25V X6S 0603" CAPC1608X09N[0603] 5810,2160 r90 top value=4.7E-6
C53 "50V X7R 0603" CAPC1608X09N[0603] 3660,4410 r270 bottom value=1E-7
C54 "50V X7R 0603" CAPC1608X09N[0603] 3910,4630 r0 bottom value=3.3E-8
C55 "50V X7R 0603" CAPC1608X09N[0603] 3910,4560 r0 bottom value=1E-7
C56 "50V X7R 0603" CAPC1608X09N[0603] 4000,4420 r90 bottom value=3.3E-8
C57 "50V X7R 0603" CAPC1608X09N[0603] 3890,4420 r90 bottom value=1E-7
C58 "50V X7R 0603" CAPC1608X09N[0603] 3758.5,4260 r180 bottom value=3.3E-8
C59 "50V X7R 0603" CAPC1608X09N[0603] 3760,4350 r180 bottom value=1E-7
C60 "50V X7R 0603" CAPC1608X09N[0603] 3570,4540 r90 bottom value=3.3E-8
C61 "50V X7R 0603" CAPC1608X09N[0603] 3660,4540 r90 bottom value=1E-7
C62 "50V X7R 0603" CAPC1608X09N[0603] 5650,5260 r270 bottom value=3.3E-8
C63 "50V X7R 0603" CAPC1608X09N[0603] 5740,2160 r90 top value=1E-7
C64 "25V X6S 0603" CAPC1608X09N[0603] 3190,3181.5 r270 bottom value=4.7E-6
C65 "25V X6S 0603" CAPC1608X09N[0603] 2930,3171.5 r270 bottom value=4.7E-6
C66 "50V C0G 0603" CAPC1608X09N[0603] 5670,2160 r90 top value=1E-9
C67 "50V X7R 0603" CAPC1608X09N[0603] 3510,4670 r270 bottom value=1E-7
C68 "50V C0G 0603" CAPC1608X09N[0603] 5100,2200 r90 top value=1E-9
C69 "50V X7R 0603" CAPC1608X09N[0603] 5104.09,2197.24 r90 bottom value=1E-7
C70 "250VAC X1/Y2" CAPC4720X22N 6770,1460 r90 top value=1E-9
C71 "250VAC X1/Y2" CAPC4720X22N 6630,1460 r270 top value=1E-9
C72 "50V X7R 0603" CAPC1608X09N[0603] 5650,4670 r0 bottom value=1E-7
C73 "25V X6S 0603" CAPC1608X09N[0603] 5194.09,2197.24 r90 bottom value=4.7E-6
C74 "50V X7R 0603" CAPC1608X09N[0603] 5570,4380 r270 bottom value=1E-7
C75 "50V X7R 0603" CAPC1608X09N[0603] 6080,4330 r270 bottom value=1E-7
C76 "25V X6S 0603" CAPC1608X09N[0603] 5264.09,2197.24 r90 bottom value=4.7E-6
C77 "50V X7R 0603" CAPC1608X09N[0603] 6110,2160 r270 top value=3.3E-8
C78 "50V X7R 0603" CAPC1608X09N[0603] 5970,2160 r270 top value=3.3E-8
C79 "50V X7R 0603" CAPC1608X09N[0603] 6084.09,2787.24 r270 top value=3.3E-8
C80 "25V X6S 0603" CAPC1608X09N[0603] 5944.09,2787.24 r90 top value=4.7E-6
C81 "50V X7R 0603" CAPC1608X09N[0603] 5874.09,2787.24 r90 top value=1E-7
C82 "25V X6S 0603" CAPC1608X09N[0603] 5734.09,2787.24 r90 top value=4.7E-6
C83 "50V X7R 0603" CAPC1608X09N[0603] 5804.09,2787.24 r90 top value=1E-7
C84 "250VAC X1/Y2" CAPC4720X22N 5564.88,2777.24 r180 top value=2.2E-10
C85 "250VAC X1/Y2" CAPC4720X22N 5314.09,2777.24 r180 top value=2.2E-10
C86 "50V X7R 0603" CAPC1608X09N[0603] 6014.09,2787.24 r90 top value=3.3E-8
C87 "50V X7R 0603" CAPC1608X09N[0603] 4660.28,4513.13 r270 bottom value=1E-7
C88 "50V X7R 0603" CAPC1608X09N[0603] 3720,4670 r90 bottom value=3.3E-8
C89 "50V X7R 0603" CAPC1608X09N[0603] 3650,4670 r90 bottom value=1E-7
C90 "50V X7R 0603" CAPC1608X09N[0603] 1332.99,3440 r180 top value=1E-7
C91 "50V X7R 0603" CAPC1608X09N[0603] 1581.5,3300 r90 top value=1E-7
C92 "16V  X5R 1210" CAPC3225X270 1701.5,3290 r90 top value=4.7E-5
C93 "50V C0G 0603" CAPC1608X09N[0603] 320,3352.87 r90 bottom value=1E-9
C94 "100V X5R 1210" CAPC3225X270 1570,3500 r270 top value=4.7E-6
C95 "100V X5R 1210" CAPC3225X270 1850,3500 r270 top value=4.7E-6
C96 "50V X7R 0603" CAPC1608X09N[0603] 1301.5,3740 r0 bottom value=2.2E-8
C97 "50V C0G 0603" CAPC1608X09N[0603] 1301.5,3810 r0 bottom value=1.6E-11
C98 "50V X7R 0603" CAPC1608X09N[0603] 1057.13,4150 r180 top value=1E-7
C99 "50V X7R 0603" CAPC1608X09N[0603] 1297.13,4030 r90 top value=1E-7
C100 "16V  X5R 1210" CAPC3225X270 1407.13,4010 r90 top value=4.7E-5
C101 "50V C0G 0603" CAPC1608X09N[0603] 320,3662.87 r90 bottom value=1E-9
C102 "100V X5R 1210" CAPC3225X270 1280,4230 r270 top value=4.7E-6
C103 "100V X5R 1210" CAPC3225X270 1560,4230 r270 top value=4.7E-6
C104 "50V X7R 0603" CAPC1608X09N[0603] 987.13,4450 r0 bottom value=2.2E-8
C105 "50V C0G 0603" CAPC1608X09N[0603] 987.13,4520 r0 bottom value=1.6E-11
C106 "50V X7R 0603" CAPC1608X09N[0603] 2530,1510 r0 bottom value=1E-7
C107 "50V C0G 0603" CAPC1608X09N[0603] 2800,1618.5 r270 bottom value=1E-8
C108 "50V C0G 0603" CAPC1608X09N[0603] 2730,1618.5 r270 bottom value=1E-8
C109 "50V C0G 0603" CAPC1608X09N[0603] 2370,1618.5 r270 bottom value=1E-8
C110 "50V C0G 0603" CAPC1608X09N[0603] 2300,1618.5 r270 bottom value=1E-8
C111 "50V X7R 0603" CAPC1608X09N[0603] 2690,3930 r270 bottom value=1E-7
C112 "50V C0G 0603" CAPC1608X09N[0603] 2632.87,4200 r0 bottom value=1E-8
C113 "50V C0G 0603" CAPC1608X09N[0603] 2632.87,4130 r0 bottom value=1E-8
C114 "50V C0G 0603" CAPC1608X09N[0603] 2550,3732.87 r90 bottom value=1E-8
C115 "50V C0G 0603" CAPC1608X09N[0603] 2620,3732.87 r90 bottom value=1E-8
C116 "80V Can 20% 320mO" CAPAE1300X1350D1370DD420L475N 2010,2999.06 r270 top value=6.8E-5
C117 "100V X5R 1210" CAPC3225X270 2040,3720 r0 top value=4.7E-6
C118 "80V Can 20% 320mO" CAPAE1300X1350D1370DD420L475N 2159.06,4200 r0 top value=6.8E-5
C119 "100V X5R 1210" CAPC3225X270 1737.13,4270 r0 top value=4.7E-6
C120 "80V Can 20% 320mO" CAPAE1300X1350D1370DD420L475N 4530,2360 r90 top value=6.8E-5
C121 "100V X5R 1210" CAPC3225X270 3900,1630 r270 top value=4.7E-6
C122 "50V X7R 0603" CAPC1608X09N[0603] 1220.63,4892.44 r270 bottom value=1E-7
C123 "100V X5R 1210" CAPC3225X270 2040,3590 r0 top value=4.7E-6
C124 "100V X5R 1210" CAPC3225X270 2040,3850 r0 top value=4.7E-6
C125 "100V X5R 1210" CAPC3225X270 1710,3500 r270 top value=4.7E-6
C126 "100V X5R 1210" CAPC3225X270 1737.13,4540 r0 top value=4.7E-6
C127 "100V X5R 1210" CAPC3225X270 1737.13,4400 r0 top value=4.7E-6
C128 "100V X5R 1210" CAPC3225X270 1420,4230 r270 top value=4.7E-6
C129 "100V X5R 1210" CAPC3225X270 4040,1630 r270 top value=4.7E-6
C130 "100V X5R 1210" CAPC3225X270 4180,1630 r270 top value=4.7E-6
C131 "100V X5R 1210" CAPC3225X270 4030,2170 r270 top value=4.7E-6
C132 "100V X5R 1210" CAPC3225X270 4150,2360 r90 top value=4.7E-6
C133 "25V X6S 0603" CAPC1608X09N[0603] 1980,2228.5 r90 top value=4.7E-6
C134 "25V X6S 0603" CAPC1608X09N[0603] 2170,2575 r270 top value=4.7E-6
C135 "50V X7R 0603" CAPC1608X09N[0603] 2250,2575.39 r270 top value=1E-7
C136 "100V X5R 1210" CAPC3225X270 910,1176.54 r180 top value=4.7E-6
C137 "100V X5R 1210" CAPC3225X270 910,1316.54 r180 top value=4.7E-6
C138 "100V X5R 1210" CAPC3225X270 910,1456.54 r180 top value=4.7E-6
C139 "100V X5R 1210" CAPC3225X270 1840,2521.5 r0 top value=4.7E-6
C140 "100V X5R 1210" CAPC3225X270 1840,2390 r0 top value=4.7E-6
C141 "100V X5R 1210" CAPC3225X270 1630,2650 r180 top value=4.7E-6
C142 "100V X5R 1210" CAPC3225X270 1630,2520 r180 top value=4.7E-6
C143 "100V X5R 1210" CAPC3225X270 1630,2390 r180 top value=4.7E-6
C144 "50V C0G 0603" CAPC1608X09N[0603] 2500,2565.39 r90 top value=1E-8
C145 "25V X6S 0603" CAPC1608X09N[0603] 2570,2565.39 r270 top value=4.7E-6
C146 "50V X7R 0603" CAPC1608X09N[0603] 2660,2564.41 r270 top value=1E-7
C147 "100V X7S 0805" CAPC2012X135 1980,2090 r90 top value=4.7E-7
C148 "50V X5R 1206" CAPC3216X180 1420,2501.5 r0 top value=1E-5
C149 "50V X5R 1206" CAPC3216X180 1420,2591.5 r0 top value=1E-5
C150 "50V X5R 1206" CAPC3216X180 1420,2681.5 r0 top value=1E-5
C151 "50V X5R 1206" CAPC3216X180 1420,2771.5 r0 top value=1E-5
C152 "50V X7R 0603" CAPC1608X09N[0603] 1290,2850 r90 top value=1E-7
C153 "50V C0G 0603" CAPC1608X09N[0603] 450,2751.5 r90 bottom value=1E-9
C154 "100V X7S 0805" CAPC2012X135 2490,2137.05 r90 top value=4.7E-7
C155 "50V C0G 0603" CAPC1608X09N[0603] 2540,1950 r270 top value=3.3E-11
C156 "100V X7S 0805" CAPC2012X135 2610,1950 r270 top value=4.7E-7
C157 "50V X7R 0603" CAPC1608X09N[0603] 2630,2131.5 r90 top value=1E-7
C158 "50V C0G 0603" CAPC1608X09N[0603] 2000,2360 r270 top value=1E-10
C159 "50V C0G 0603" CAPC1608X09N[0603] 1820,1780 r180 top value=1E-9
C160 "50V C0G 0603" CAPC1608X09N[0603] 2791.49,2271.5 r270 top value=1E-9
C161 "50V C0G 0603" CAPC1608X09N[0603] 2721.49,2271.5 r90 top value=1.6E-11
C162 "50V C0G 0603" CAPC1608X09N[0603] 2651.49,2271.5 r90 top value=1E-8
C163 "50V X7R 0603" CAPC1608X09N[0603] 2661.5,2180 r0 bottom value=1E-7
C164 "50V X7R 0603" CAPC1608X09N[0603] 2661.5,2320 r0 bottom value=1E-7
C165 "50V C0G 0603" CAPC1608X09N[0603] 2320,2451.5 r90 bottom value=1E-8
C166 "50V X7R 0603" CAPC1608X09N[0603] 2521.5,2180 r180 bottom value=1E-7
C167 "50V X7R 0603" CAPC1608X09N[0603] 2521.5,2320 r180 bottom value=1E-7
C168 "50V X7R 0603" CAPC1608X09N[0603] 2610,2740 r180 bottom value=1E-7
C169 "50V X7R 0603" CAPC1608X09N[0603] 2610,3000 r0 bottom value=1E-7
C170 "50V X7R 0603" CAPC1608X09N[0603] 2870,2960 r270 bottom value=1E-7
C171 "50V C0G 0603" CAPC1608X09N[0603] 2740,3140 r0 bottom value=1E-8
C172 "50V C0G 0603" CAPC1608X09N[0603] 2740,3070 r0 bottom value=1E-8
C173 "50V C0G 0603" CAPC1608X09N[0603] 2740,2740 r0 bottom value=1E-8
C174 "50V C0G 0603" CAPC1608X09N[0603] 2740,2670 r0 bottom value=1E-8
C175 "50V X7R 0603" CAPC1608X09N[0603] 2180,1560 r0 bottom value=1E-7
C176 "50V X7R 0603" CAPC1608X09N[0603] 2080,1660 r270 bottom value=1E-7
C177 "50V C0G 0603" CAPC1608X09N[0603] 3080,2478.5 r180 bottom value=1E-9
C178 "50V X7R 0603" CAPC1608X09N[0603] 2470,3730 r270 bottom value=1E-7
C179 "50V X7R 0603" CAPC1608X09N[0603] 2530,4161.5 r90 bottom value=1E-7
C180 "50V X7R 0603" CAPC1608X09N[0603] 2358.5,2560 r180 bottom value=1E-7
C181 "16V  X5R 1210" CAPC3225X270 3128.07,3465.52 r180 top value=4.7E-5
C182 "50V X7R 0603" CAPC1608X09N[0603] 4720,2915.43 r180 bottom value=1E-7
C183 "50V X7R 0603" CAPC1608X09N[0603] 2012.78,2501.5 r90 top value=1E-7
C184 "25V X6S 0603" CAPC1608X09N[0603] 2288.8,2437.24 r90 top value=4.7E-6
C185 "25V X6S 0603" CAPC1608X09N[0603] 1310,4897.83 r270 bottom value=4.7E-6
C186 "50V C0G 0603" CAPC1608X09N[0603] 923.99,4897.38 r270 bottom value=1E-8
C187 "25V X6S 0603" CAPC1608X09N[0603] 763.99,4897.38 r270 bottom value=4.7E-6
C188 "50V X7R 0603" CAPC1608X09N[0603] 843.99,4897.38 r270 bottom value=1E-7
CX1 "100V 5%" CAPC3216X100 5740,761.18 r90 bottom value=2.2E-8
CX2 "275VAC X2" CAP_RAD15P1805X11 5290,3744.72 r270 top value=2.2E-8
D1 "RED" LEDC1608X06NRED,0603, 3220,4350 r180 top
D2 "40V 500mA" SOD-123 3015.35,3310 r180 bottom
D3 "YEL" LEDC1608X06NYEL,0603, 3220,4130 r180 top
D4 "1N4148" SOD-123 5098.5,1635.35 r90 bottom
D5 "1N4148" SOD-123 5098.5,1420 r90 bottom
D6 "1N4148" SOD-123 5008.5,1640 r90 bottom
D7 "1N4148" SOD-123 4928.5,1845.35 r90 bottom
D8 "TVS" DO-214AB_SMC_BIDIR 5400,740 r270 top
D9 "40V 500mA" SOD-123 3190,3374.65 r90 bottom
D10 "TVS" SOT23-6 4520,5050 r0 bottom
D11 "TVS" SOT23-6 610,1660 r270 bottom
D12 "60V 20A" TO-277_Z3N 3864.8,1980 r90 top
D13 "10V 1W" DO-214AC 5520,1300 r180 bottom
D14 "1000V 1A" DO-214AC 6500,4930 r270 bottom
D15 "1000V 1A" DO-214AC 6710,4930 r270 bottom
D16 "8.2V 1W" DO-214AC 5800,5040 r270 bottom
D17 "4000V 250mA" DO-204AL[DO-41] 5710,5360 r0 top
D18 "RED" LEDC1608X06NRED,0603, 5340,4710 r0 top
D19 "1N4148" SOD-123 5410,4260 r0 top
D20 "1N4148" SOD-123 6350,4490 r90 bottom
D21 "1N4148" SOD-123 6350,4240 r270 bottom
D22 "1N4148" SOD-123 6090,4330 r270 top
D23 "5.6V 200mW" SOD-323F 1540,3870 r180 top
D24 "TVS" SOT23-6 3000,5070 r270 bottom
D25 "1000V 1A" DO-214AC 490,5300 r270 bottom
D26 "TVS" SOT23-6 3100,5361.1 r90 bottom
D27 "1N4148" SOD-123 6054.09,2287.24 r180 top
D28 "1N4148" SOD-123 4928.5,1640 r90 bottom
D29 "24WVM" DO-214AC 6120,5040 r270 bottom
D30 "TVS" SOT23-6 2180,4890 r0 bottom
D31 "GRN" LEDC1608X06NGRN,0603, 3220,3910 r180 top
D32 "1N4148" SOD-123 5008.5,1845.35 r90 bottom
D33 "1N4148" SOD-123 5844.09,2367.24 r180 top
D34 "1N4148" SOD-123 5844.09,2287.24 r180 top
D35 "1N4148" SOD-123 6054.09,2367.24 r180 top
D36 "1N4148" SOD-123 5804.09,2487.24 r180 top
D37 "1N4148" SOD-123 5804.09,2567.24 r180 top
D38 "1000V 1A" DO-214AC 6500,5220 r270 bottom
D39 "1000V 1A" DO-214AC 6710,5220 r270 bottom
D40 "8.2V 1W" DO-214AC 5640,5040 r270 bottom
D41 "60V 20A" TO-277_Z3N 1324.8,3306.22 r90 top
D42 "60V 20A" TO-277_Z3N 1070.43,4010 r90 top
D43 "60V 20A" TO-277_Z3N 4460,1610 r90 top
D44 "60V 20A" TO-277_Z3N 3673.39,1570 r270 top
D45 "TVS" SOT23-6 654.44,4647.8 r0 bottom
D46 "40V 500mA" SOD-123 2480,1820 r0 top
D47 "1N4148" SOD-123 2040,1780 r180 top
D48 "80V 500mA" SOD-123 1900,2125.95 r90 top
D49 "5.6V 200mW" SOD-323F 1245.8,4555 r180 top
D50 "5.6V 200mW" SOD-323F 4010,2500 r180 top
D51 "12VWM" SOT23-3B 2852.6,1650 r0 top
D52 "TVS" SOT23-6 3376.84,3518.65 r270 bottom
D53 "TVS" SOT23-6 4180.98,5302.25 r180 bottom
D54 "40V 500mA" SOD-123 2501.8,2451.25 r0 top
D55 "TVS" SOT23-6 4560,4680 r180 bottom
D56 "TVS" SOT23-6 620,4800 r180 bottom
D57 "12VWM" SOT23-3B 1120,5240 r0 top
D58 "TVS" SOT23-6 1669.99,5073.83 r90 bottom
F3 "15V 3A" FUSC7351X12N[2920] 1560,5350 r0 top
F4 "1.1A 16V" Fuse-Bourns-MF-MSMF050-2 1660,5090 r90 top
F5 "1.1A 16V" Fuse-Bourns-MF-MSMF050-2 680,5390 r180 top
FC1 "MINI" KEYSTONE_3568 7460,170 r180 top
FC3 "5x20mm clip" SCHURTER_0751.0110 7700,3610 r90 top
FC4 "5x20mm clip" SCHURTER_0751.0110 7700,4210 r270 top
GDT1 "75Vdc breakdown" LITTELFUSE_SL1411A 7320,560 r90 top value=75
GDT2 "75Vdc breakdown" LITTELFUSE_SL1411A 7240,1900 r90 top value=75
GDT3 "1500Vdc breakdown" LITTELFUSE_CG3x 7290,3900 r300 top value=1500
GDT4 "2500Vdc breakdown" LITTELFUSE_CG3x 6870,2090 r270 top value=2500
GDT5 "2500Vdc breakdown" LITTELFUSE_CG3x 7470,2310 r270 top value=2500
JP1 "JST VL" JST_B02P-VL 7700,1222.05 r270 top locked
JP2 "QC 6.35mm" AMP_63849-1 7800,2000 r270 top locked
JP3 "1x5_odd (3.96mm)" AMP_1-1123724-3 4510,3520 r90 top locked
JP4 "MLX" MOLEX_432550059 7700,2950 r90 top locked
JP5 "JST VL" JST_B03P-VL 260,2630 r90 top locked
JP6 "1x7 3.96mm blue" AMP_1-1123723-7 250,1540 r90 top locked
JP7 "JST XH" JST_B4B-XH-AM(LF)(SN) 160,5230 r270 top locked
JP8 "1x2 3.96mm" AMP_1-1123723-2 200,230 r90 top locked
JP9 "2x8 2mm" MOLEX_0559171610 2360,5220 r180 top locked
JP10 "TC2030" TAG-TC2030-LEGS 3410,5270 r180 top locked
JP11 "2x5 1.27mm" CNC_3220-10-0100-00 3880,5335 r270 top locked
JP12 "1x6 0.1in" HDR_6PIN 4730,5320 r0 top locked
JP13 "1x4 3.96mm" AMP_1-1123723-4 230,3502.87 r90 top locked
JP14 "1x5 2.5mm" JST_B5B-XH-A(LF)(SN) 160,4248.43 r270 top locked
JY1 "1x3 0.1in" HDR_3PIN 2820,4760 r0 top locked
JY2 "1x3 0.1in" HDR_3PIN 2820,4610 r0 top locked
JY5 "JST XH" JST_B2B-XH-AM(LF)(SN) 3280,3680 r180 top locked
JY6 "2x8 0.1\"" SULLINS_PRPC008DAAN-RC 4850,4720 r270 top locked
JY8 "1x3 0.1in" HDR_3PIN 2820,4400 r0 top locked
K1 "SPST 12V" TE_RT1_2COIL_LATCHING 6740,4390 r90 top
L1 "20A 2.8mOhm" WURTH_S14100038 6050,761.18 r270 top value=0.00056
L2 "22A 4mOhm" INDUCTOR-BOURNS_SRP1270 1290,1320 r90 top value=2.2E-6
L3 "19A 9mOhm" INDUCTOR_VISHAY_IHLP-6767 980,2160 r90 top value=1E-5
L4 "170 Ohm 20A" LAIRD_CM3443Z171R-10 794.96,2870 r270 top value=170
L5 "1k Ohm 0.5A" INDC2012X110N[0805] 4770,1120 r180 bottom value=1000
L6 "9A 37mOhm" INDUCTOR_VISHAY_IHLP-6767 3290.55,2071.93 r270 top value=3.3E-5
L7 "785 Ohm 3A" INDC4532X17N[1812] 7450,4210 r180 top value=785
L8 "1k Ohm 0.5A" INDC2012X110N[0805] 170,3090 r180 bottom value=1000
L9 "6A 19.5mOhm" INDUCTOR-BOURNS_SRR1280 3170,3118.5 r90 top value=1E-5
L10 "20A 4.1mOhm" PULSE_HCCI-80 6049.21,760 r270 top value=0.00038
L11 "1k Ohm 0.5A" INDC2012X110N[0805] 3760,4460 r270 bottom value=1000
L12 "1k Ohm 0.5A" INDC2012X110N[0805] 324.57,5110 r180 bottom value=1000
L13 "170 Ohm 20A" LAIRD_CM3443Z171R-10 6850,510 r270 top value=170
L14 "785 Ohm 3A" INDC4532X17N[1812] 420,5390 r180 top value=785
L15 "785 Ohm 3A" INDC4532X17N[1812] 420,5240 r180 top value=785
L16 "6A 15mOhm" INDUCTOR-BOURNS_SRN6045 1781.5,3730 r180 top value=2.2E-6
L17 "785 Ohm 3A" INDC4532X17N[1812] 4600,4000 r180 top value=785
L18 "2.2A 110mOhm" TDK_B82732R 5760,3690 r270 top value=0.0033
L19 "785 Ohm 3A" INDC4532X17N[1812] 5060,3710 r180 top value=785
L20 "785 Ohm 3A" INDC4532X17N[1812] 7430,2820 r90 top value=785
L27 "785 Ohm 3A" INDC4532X17N[1812] 1860,5200 r0 top value=785
L28 "785 Ohm 3A" INDC4532X17N[1812] 1860,5370 r180 top value=785
L33 "785 Ohm 3A" INDC4532X17N[1812] 2870,5230 r0 top value=785
L34 "2A 100mOhm" KEMET_SCxx-yyGJ_17X17MM 5760,3690 r270 top value=0.003
L35 "1k Ohm 0.5A" INDC2012X110N[0805] 6430,2370 r270 top value=1000
L39 "9A 37mOhm" INDUCTOR_VISHAY_IHLP-6767 811.5,3480 r270 top value=3.3E-5
L40 "26 ohm 6A" FER1608X100[0603] 350,3242.87 r180 bottom value=26
L41 "26 ohm 6A" FER1608X100[0603] 356.54,3452.87 r180 bottom value=26
L42 "6A 19.5mOhm" INDUCTOR-BOURNS_SRR1280 617.13,4220 r270 top value=1E-5
L43 "26 ohm 6A" FER1608X100[0603] 350,3562.87 r180 bottom value=26
L44 "26 ohm 6A" FER1608X100[0603] 350,3762.87 r180 bottom value=26
L45 "6A 15mOhm" INDUCTOR-BOURNS_SRN6045 1487.13,4480 r180 top value=2.2E-6
L46 "6A 15mOhm" INDUCTOR-BOURNS_SRN6045 4370,1860 r90 top value=2.2E-6
L47 "100 Ohm 8A" INDC4532X17N[1812] 520,310 r180 top value=100
L48 "100 Ohm 8A" INDC4532X17N[1812] 520,120 r180 top value=100
L49 "100 Ohm 8A" INDC4532X17N[1812] 540,1090 r90 top value=100
L50 "100 Ohm 8A" INDC4532X17N[1812] 530,1920 r90 top value=100
LA1 "600 Ohm 200mA" FERCAV80P320X160X70-4 2750,5390 r0 bottom value=600
LA2 "600 Ohm 200mA" FERCAV80P320X160X70-4 2177.24,5030.47 r270 bottom value=600
LA3 "600 Ohm 200mA" FERCAV80P320X160X70-4 2820.47,5214.25 r0 bottom value=600
LA4 "600 Ohm 200mA" FERCAV80P320X160X70-4 430,1690 r180 bottom value=600
LA5 "600 Ohm 200mA" FERCAV80P320X160X70-4 6240,2690 r180 top value=600
LA6 "600 Ohm 200mA" FERCAV80P320X160X70-4 5060,1230 r90 bottom value=600
LA7 "600 Ohm 200mA" FERCAV80P320X160X70-4 4580,5190 r270 bottom value=600
LA8 "600 Ohm 200mA" FERCAV80P320X160X70-4 486.61,4642.8 r0 bottom value=600
MECH1 "jumper" SULLINS_QPC02SXGN-RC 2770,4760 r180 top
MECH2 "10C/W" RESC2012X06N[0805] 1400,740 r270 bottom
MECH3 "jumper" SULLINS_QPC02SXGN-RC 2770,4610 r180 top
MECH4 "jumper" SULLINS_QPC02SXGN-RC 2770,4400 r180 top
MECH5 "10C/W" RESC2012X06N[0805] 850,930 r180 bottom
MECH6 "10C/W" RESC2012X06N[0805] 1460,1780 r270 top
NT1 "Net Tie" NETTIE1608X05AN[0603] 5000,1108.51 r270 bottom net-tie
NT2 "Net Tie" NETTIE_0.254mm_NOPADS#1 2340,3530 r0 top net-tie
NT3 "Net Tie" NETTIE_0.254mm_NOPADS#1 1770,3950 r0 top net-tie
NT4 "Net Tie" NETTIE_0.254mm_NOPADS#1 540,1430 r90 top net-tie
NT5 "Net Tie" NETTIE_0.254mm_NOPADS#1 720,1430 r90 top net-tie
NT6 "Net Tie" NETTIE_0.254mm_NOPADS#2 2770,4400 r180 top net-tie
Q1 "N-CH 60V 30A" SOT1205_LFPAK56D 1640,820 r180 top
Q2 "N-CH 60V 30A" SOT1205_LFPAK56D 2140,820 r0 top
Q3 "N-CH 60V 30A" SOT1205_LFPAK56D 3330,1020 r270 top
Q4 "N-CH 60V 29A" "SOIC-8 PPAK" 511.63,893.55 r0 top
Q5 "60V 300mA" SOT23-3#1 3000,3780 r270 bottom
Q6 "60V 300mA" SOT23-3#1 2860,3780 r270 bottom
Q7 "N-CH 30V 3.4A" SOT23-3#2 820,5200 r270 bottom
Q8 "DUAL P 30V" SOT_23_6 941.7,5360 r180 bottom
Q9 "N-CH 30V 3.4A" SOT23-3#2 2720,3780 r0 bottom
Q10 "N-CH 30V 3.4A" SOT23-3#2 1491.49,5371.86 r270 bottom
Q11 "N-CH 30V 3.4A" SOT23-3#2 4681.42,1515.65 r0 bottom
Q12 "60V 300mA" SOT23-3#2 3070,3560 r0 bottom
Q13 "DUAL P 30V" SOT_23_6 1255.63,5323.15 r90 bottom
Q14 "N-CH 30V 3.4A" SOT23-3#2 2239,1070 r270 bottom
Q15 "60V 300mA" SOT23-3#1 5370,5110 r180 bottom
Q16 "N-CH 30V 3.4A" SOT23-3#2 6470,4530 r180 bottom
Q17 "N-CH 30V 3.4A" SOT23-3#2 6470,4220 r0 bottom
Q18 "N-CH 30V 3.4A" SOT23-3#2 1541.5,3760 r90 bottom
Q19 "N-CH 30V 3.4A" SOT23-3#2 1258.13,4460 r90 bottom
Q20 "N-CH 60V 30A" SOT1205_LFPAK56D 840,270 r180 top
Q21 "DUAL P 30V" SOT_23_6 1832.19,5014.78 r270 bottom
Q22 "N-CH 30V 3.4A" SOT23-3#2 1580,5207.95 r90 bottom
Q23 "DUAL P 30V" SOT_23_6 2900,3973.15 r270 bottom
Q24 "N-CH 30V 3.4A" SOT23-3#2 2910,4213.15 r270 bottom
Q25 "N-CH 30V 3.4A" SOT23-3#2 2061,1067.4 r270 bottom
Q26 "N-CH 60V 29A" "SOIC-8 PPAK" 1151.63,893.55 r0 top
Q27 "N-CH 60V 29A" "SOIC-8 PPAK" 1068.37,746.45 r180 top
Q28 "N-CH 60V 29A" "SOIC-8 PPAK" 5261.63,1163.55 r0 top
Q29 "N-CH 30V 3.4A" SOT23-3#2 1840,1160 r90 bottom
Q30 "N-CH 60V 29A" "SOIC-8 PPAK" 1640,2051.5 r90 top
Q31 "N-CH 30V 3.4A" SOT23-3#2 2120,1940 r180 bottom
Q32 "N-CH 60V 29A" "SOIC-8 PPAK" 1533.55,2099.87 r270 top
Q33 "DUAL P 30V" SOT_23_6 2440,1961.5 r0 bottom
Q34 "N-CH 30V 3.4A" SOT23-3#2 2270,1821.5 r270 bottom
Q35 "DUAL P 30V" SOT_23_6 2670,1961.5 r180 bottom
Q36 "N-CH 30V 3.4A" SOT23-3#2 2930,1971.5 r180 bottom
Q37 "2907" SOT23-3#1 2040,2378.5 r270 bottom
Q38 "N-CH 30V 3.4A" SOT23-3#2 2620,1830 r270 bottom
Q39 "DUAL P 30V" SOT_23_6 3380.95,2315.43 r90 bottom
Q40 "N-CH 30V 3.4A" SOT23-3#2 3230.95,2149.43 r0 bottom
R1 "1/10W 0603 1%" RESC1608X05AN[0603] 1460,5207.95 r90 bottom value=100000
R2 "25W DPAK 1%" BOURNS_PWR163 1260,362.5 r270 top value=33
R3 "1/10W 0603 1%" RESC1608X05AN[0603] 3190,4490 r90 bottom value=200
R4 "1/10W 0603 1%" RESC1608X05AN[0603] 1061.7,5330 r90 bottom value=10000
R5 "1/10W 0603 1%" RESC1608X05AN[0603] 4363.86,4507.68 r90 bottom value=4750
R6 "1/10W 0603 1%" RESC1608X05AN[0603] 4283.86,4507.68 r90 bottom value=4750
R7 "1/10W 0603 1%" RESC1608X05AN[0603] 3580,4670 r90 bottom value=100000
R8 "1/10W 0603 1%" RESC1608X05AN[0603] 4980,2560 r180 bottom value=1000000
R9 "1/10W 0603 1%" RESC1608X05AN[0603] 1832.19,5154.78 r180 bottom value=10000
R10 "35W D2PAK 1%" TO263_PWR_RES 4460,400 r270 top value=8
R11 "35W D2PAK 1%" TO263_PWR_RES 3960,400 r270 top value=8
R12 "35W D2PAK 1%" TO263_PWR_RES 3460,400 r270 top value=8
R13 "35W D2PAK 1%" TO263_PWR_RES 2960,400 r270 top value=8
R14 "35W D2PAK 1%" TO263_PWR_RES 3887.95,1210 r180 top value=8
R15 "1/10W 0603 0.1%" RESC1608X05AN[0603] 5178.5,1340 r90 bottom value=1000
R16 "1/10W 0603 0.1%" RESC1608X05AN[0603] 5018.5,1368.5 r270 bottom value=1000
R17 "1/10W 0603 1%" RESC1608X05AN[0603] 4810,2170 r0 bottom value=10000
R18 "35W D2PAK 1%" TO263_PWR_RES 4460,1152 r90 top value=8
R19 "35W D2PAK 1%" TO263_PWR_RES 2460,400 r270 top value=8
R20 "1/10W 0603 1%" RESC1608X05AN[0603] 3860,2650 r0 bottom value=4750
R21 "1/10W 0603 1%" RESC1608X05AN[0603] 3860,2720 r0 bottom value=4750
R22 "1/10W 0603 1%" RESC1608X05AN[0603] 3860,2790 r180 bottom value=4750
R23 "1/10W 0603 0.1%" RESC1608X05AN[0603] 4818.5,1480 r0 bottom value=1000
R24 "1/10W 0603 0.1%" RESC1608X05AN[0603] 4818.5,1340 r0 bottom value=1000
R25 "3W 2512 1%" RESC6534X70[2512]_mOhm 5050,960 r180 top value=0.001
R26 "35W D2PAK 1%" TO263_PWR_RES 2960,1150 r90 top value=8
R27 "25W DPAK 1%" BOURNS_PWR163 2020,360 r270 top value=33
R28 "25W DPAK 1%" BOURNS_PWR163 1640,362.5 r270 top value=33
R29 "35W D2PAK 1%" TO263_PWR_RES 2460,1152.05 r90 top value=8
R30 "1/10W 0603 1%" RESC1608X05AN[0603] 3550,2790 r180 bottom value=4750
R31 "1/10W 0603 1%" RESC1608X05AN[0603] 2770,4000 r270 bottom value=4750
R32 "1/10W 0603 1%" RESC1608X05AN[0603] 2960,3640 r90 bottom value=100000
R33 "1/10W 0603 1%" RESC1608X05AN[0603] 3550,2720 r180 bottom value=4750
R34 "1/10W 0603 0.1%" RESC1608X05AN[0603] 2880,3640 r90 bottom value=1000
R35 "1/10W 0603 1%" RESC1608X05AN[0603] 3550,2650 r0 bottom value=4750
R36 "1/10W 0603 1%" RESC1608X05AN[0603] 3130,3780 r90 bottom value=100000
R37 "1/10W 0603 1%" RESC1608X05AN[0603] 2800,3500 r270 bottom value=10000
R38 "1/10W 0603 1%" RESC1608X05AN[0603] 2880,3500 r270 bottom value=33200
R39 "1/10W 0603 1%" RESC1608X05AN[0603] 3070,3670 r180 bottom value=10000
R40 "1/10W 0603 1%" RESC1608X05AN[0603] 1255.63,5173.15 r0 bottom value=10000
R41 "1/10W 0603 1%" RESC1608X05AN[0603] 4010,2330 r180 top value=332000
R42 "1/10W 0603 1%" RESC1608X05AN[0603] 4120,2138.5 r90 bottom value=140000
R43 "1/10W 0603 1%" RESC1608X05AN[0603] 5750,1300 r0 bottom value=100000
R44 "1/10W 0603 1%" RESC1608X05AN[0603] 3671.5,2381.93 r0 bottom value=13000
R45 "1/10W 0603 1%" RESC1608X05AN[0603] 4010,2430 r0 top value=100000
R46 "1/10W 0603 1%" RESC1608X05AN[0603] 4040,2141.5 r270 bottom value=10000
R47 "1/10W 0603 1%" RESC1608X05AN[0603] 1611.49,5371.86 r90 bottom value=100000
R48 "1/10W 0603 1%" RESC1608X05AN[0603] 3848.78,2415 r180 top value=332000
R49 "1/10W 0603 1%" RESC1608X05AN[0603] 3260,4490 r90 bottom value=200
R50 "1/10W 0603 1%" RESC1608X05AN[0603] 3848.78,2485 r180 top value=140000
R51 "1/10W 0603 1%" RESC1608X05AN[0603] 1255.63,5093.15 r0 bottom value=4750
R52 "1/10W 0603 1%" RESC1608X05AN[0603] 5450,4730 r180 bottom value=1000
R53 "1/10W 0603 1%" RESC1608X05AN[0603] 5350,4378.5 r270 top value=1000000
R54 "1/10W 0603 0.1%" RESC1608X05AN[0603] 5420,4520 r270 bottom value=27400
R55 "1/10W 0603 1%" RESC1608X05AN[0603] 5490,4378.5 r90 top value=1000000
R56 "1/10W 0603 1%" RESC1608X05AN[0603] 6010,4410 r270 top value=1000000
R57 "1/10W 0603 0.1%" RESC1608X05AN[0603] 5420,4380 r90 bottom value=17400
R58 "1/10W 0603 1%" RESC1608X05AN[0603] 5470,4538.5 r270 top value=10000
R59 "1/10W 0603 1%" RESC1608X05AN[0603] 5420,4378.5 r270 top value=475000
R60 "1/10W 0603 0.1%" RESC1608X05AN[0603] 4730,1240 r90 bottom value=127000
R61 "1/10W 0603 1%" RESC1608X05AN[0603] 6470,4420 r0 bottom value=475000
R62 "1/10W 0603 1%" RESC1608X05AN[0603] 5790,4470 r90 bottom value=100000
R63 "1/10W 0603 1%" RESC1608X05AN[0603] 5790,4351.5 r90 bottom value=100000
R64 "1/10W 0603 1%" RESC1608X05AN[0603] 6010,4540 r90 top value=10000
R65 "1/10W 0603 1%" RESC1608X05AN[0603] 5940,4408.5 r90 top value=1000000
R66 "1/10W 0603 0.1%" RESC1608X05AN[0603] 6010,4470 r270 bottom value=27400
R67 "1/10W 0603 0.1%" RESC1608X05AN[0603] 5940,4540 r90 top value=27400
R68 "1/10W 0603 1%" RESC1608X05AN[0603] 6470,4330 r180 bottom value=475000
R69 "1/10W 0603 0.1%" RESC1608X05AN[0603] 6010,4330 r270 bottom value=3400
R70 "1/10W 0603 1%" RESC1608X05AN[0603] 5450,4270 r0 bottom value=200
R71 "1/10W 0603 1%" RESC1608X05AN[0603] 5730,4470 r270 bottom value=1000000
R72 "1/10W 0603 1%" RESC1608X05AN[0603] 3860,4730 r90 bottom value=4750
R73 "1/10W 0603 1%" RESC1608X05AN[0603] 3790,4670 r270 bottom value=10000
R74 "1/10W 0603 1%" RESC1608X05AN[0603] 5318.5,4730 r180 bottom value=1000
R75 "1/10W 0603 1%" RESC1608X05AN[0603] 3140,3970 r0 bottom value=511
R76 "1/10W 0603 1%" RESC1608X05AN[0603] 1141.7,5330 r270 bottom value=4750
R77 "3W 2512 1%" RESC6534X70[2512]_mOhm 7400,3170 r90 bottom value=0.001
R78 "1/10W 0603 1%" RESC1608X05AN[0603] 660,5100 r0 bottom value=4750
R79 "1/10W 0603 1%" RESC1608X05AN[0603] 660,5170 r180 bottom value=511
R80 "1/10W 0603 1%" RESC1608X05AN[0603] 3440,1530 r0 top value=100000
R81 "1/10W 0603 1%" RESC1608X05AN[0603] 5040,2970 r270 bottom value=100000
R82 "1/10W 0603 1%" RESC1608X05AN[0603] 3130,5180 r270 bottom value=100000
R83 "1/10W 0603 1%" RESC1608X05AN[0603] 3240,5380 r90 bottom value=100000
R84 "1/10W 0603 1%" RESC1608X05AN[0603] 3210,5180 r270 bottom value=100000
R85 "0.5W 2010 1%" RESC5025X60,2010, 5800,3030 r90 top value=220000
R86 "1/10W 0603 1%" RESC1608X05AN[0603] 1411.5,3769.53 r90 bottom value=100000
R87 "1/10W 0603 1%" RESC1608X05AN[0603] 2920,4103.15 r0 bottom value=10000
R88 "1/10W 0603 1%" RESC1608X05AN[0603] 3370,3198.5 r180 bottom value=52300
R89 "1/10W 0603 1%" RESC1608X05AN[0603] 3290,2558.5 r0 bottom value=10000
R90 "1/10W 0603 1%" RESC1608X05AN[0603] 3370,3128.5 r180 bottom value=10000
R91 "0.5W 2010 1%" RESC5025X60,2010, 6210,5130 r270 top value=3300000
R92 "1W 3kV 1%" RESC6534X70[2512] 6120,5360 r180 top value=1000000
R93 "1/10W 0603 1%" RESC1608X05AN[0603] 5490,4520 r270 bottom value=1000000
R94 "1/10W 0603 1%" RESC1608X05AN[0603] 5490,4380 r270 bottom value=475000
R95 "1/10W 0603 1%" RESC1608X05AN[0603] 5940,4470 r270 bottom value=1000000
R96 "1/10W 0603 1%" RESC1608X05AN[0603] 5940,4330 r270 bottom value=30100
R97 "1/10W 0603 1%" RESC1608X05AN[0603] 5760,5220 r0 bottom value=2740
R98 "1/10W 0603 1%" RESC1608X05AN[0603] 3030,4220 r270 bottom value=4750
R99 "0.5W 2010 1%" RESC5025X60,2010, 6356.46,2170 r180 top value=3300000
R100 "1/10W 0603 1%" RESC1608X05AN[0603] 6180,2160 r90 top value=1000
R101 "1/10W 0603 1%" RESC1608X05AN[0603] 6040,2160 r90 top value=1000
R102 "1/10W 0603 1%" RESC1608X05AN[0603] 5674.09,2327.24 r90 top value=200
R103 "1/10W 0603 1%" RESC1608X05AN[0603] 6050,2660 r0 top value=1000
R104 "1/10W 0603 1%" RESC1608X05AN[0603] 6050,2590 r180 top value=1000
R105 "1W 2512 5%" RESC6534X70[2512] 5980,4740 r180 top value=100
R106 "1/10W 0603 0.1%" RESC1608X05AN[0603] 5390,5350 r0 bottom value=27400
